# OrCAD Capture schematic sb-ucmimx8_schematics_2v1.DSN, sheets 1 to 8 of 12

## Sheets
1 01. Block Diagram: size C; title: SB-UCM-iMX8M    01. INDEX; rev: 2.0; note: 8010055003
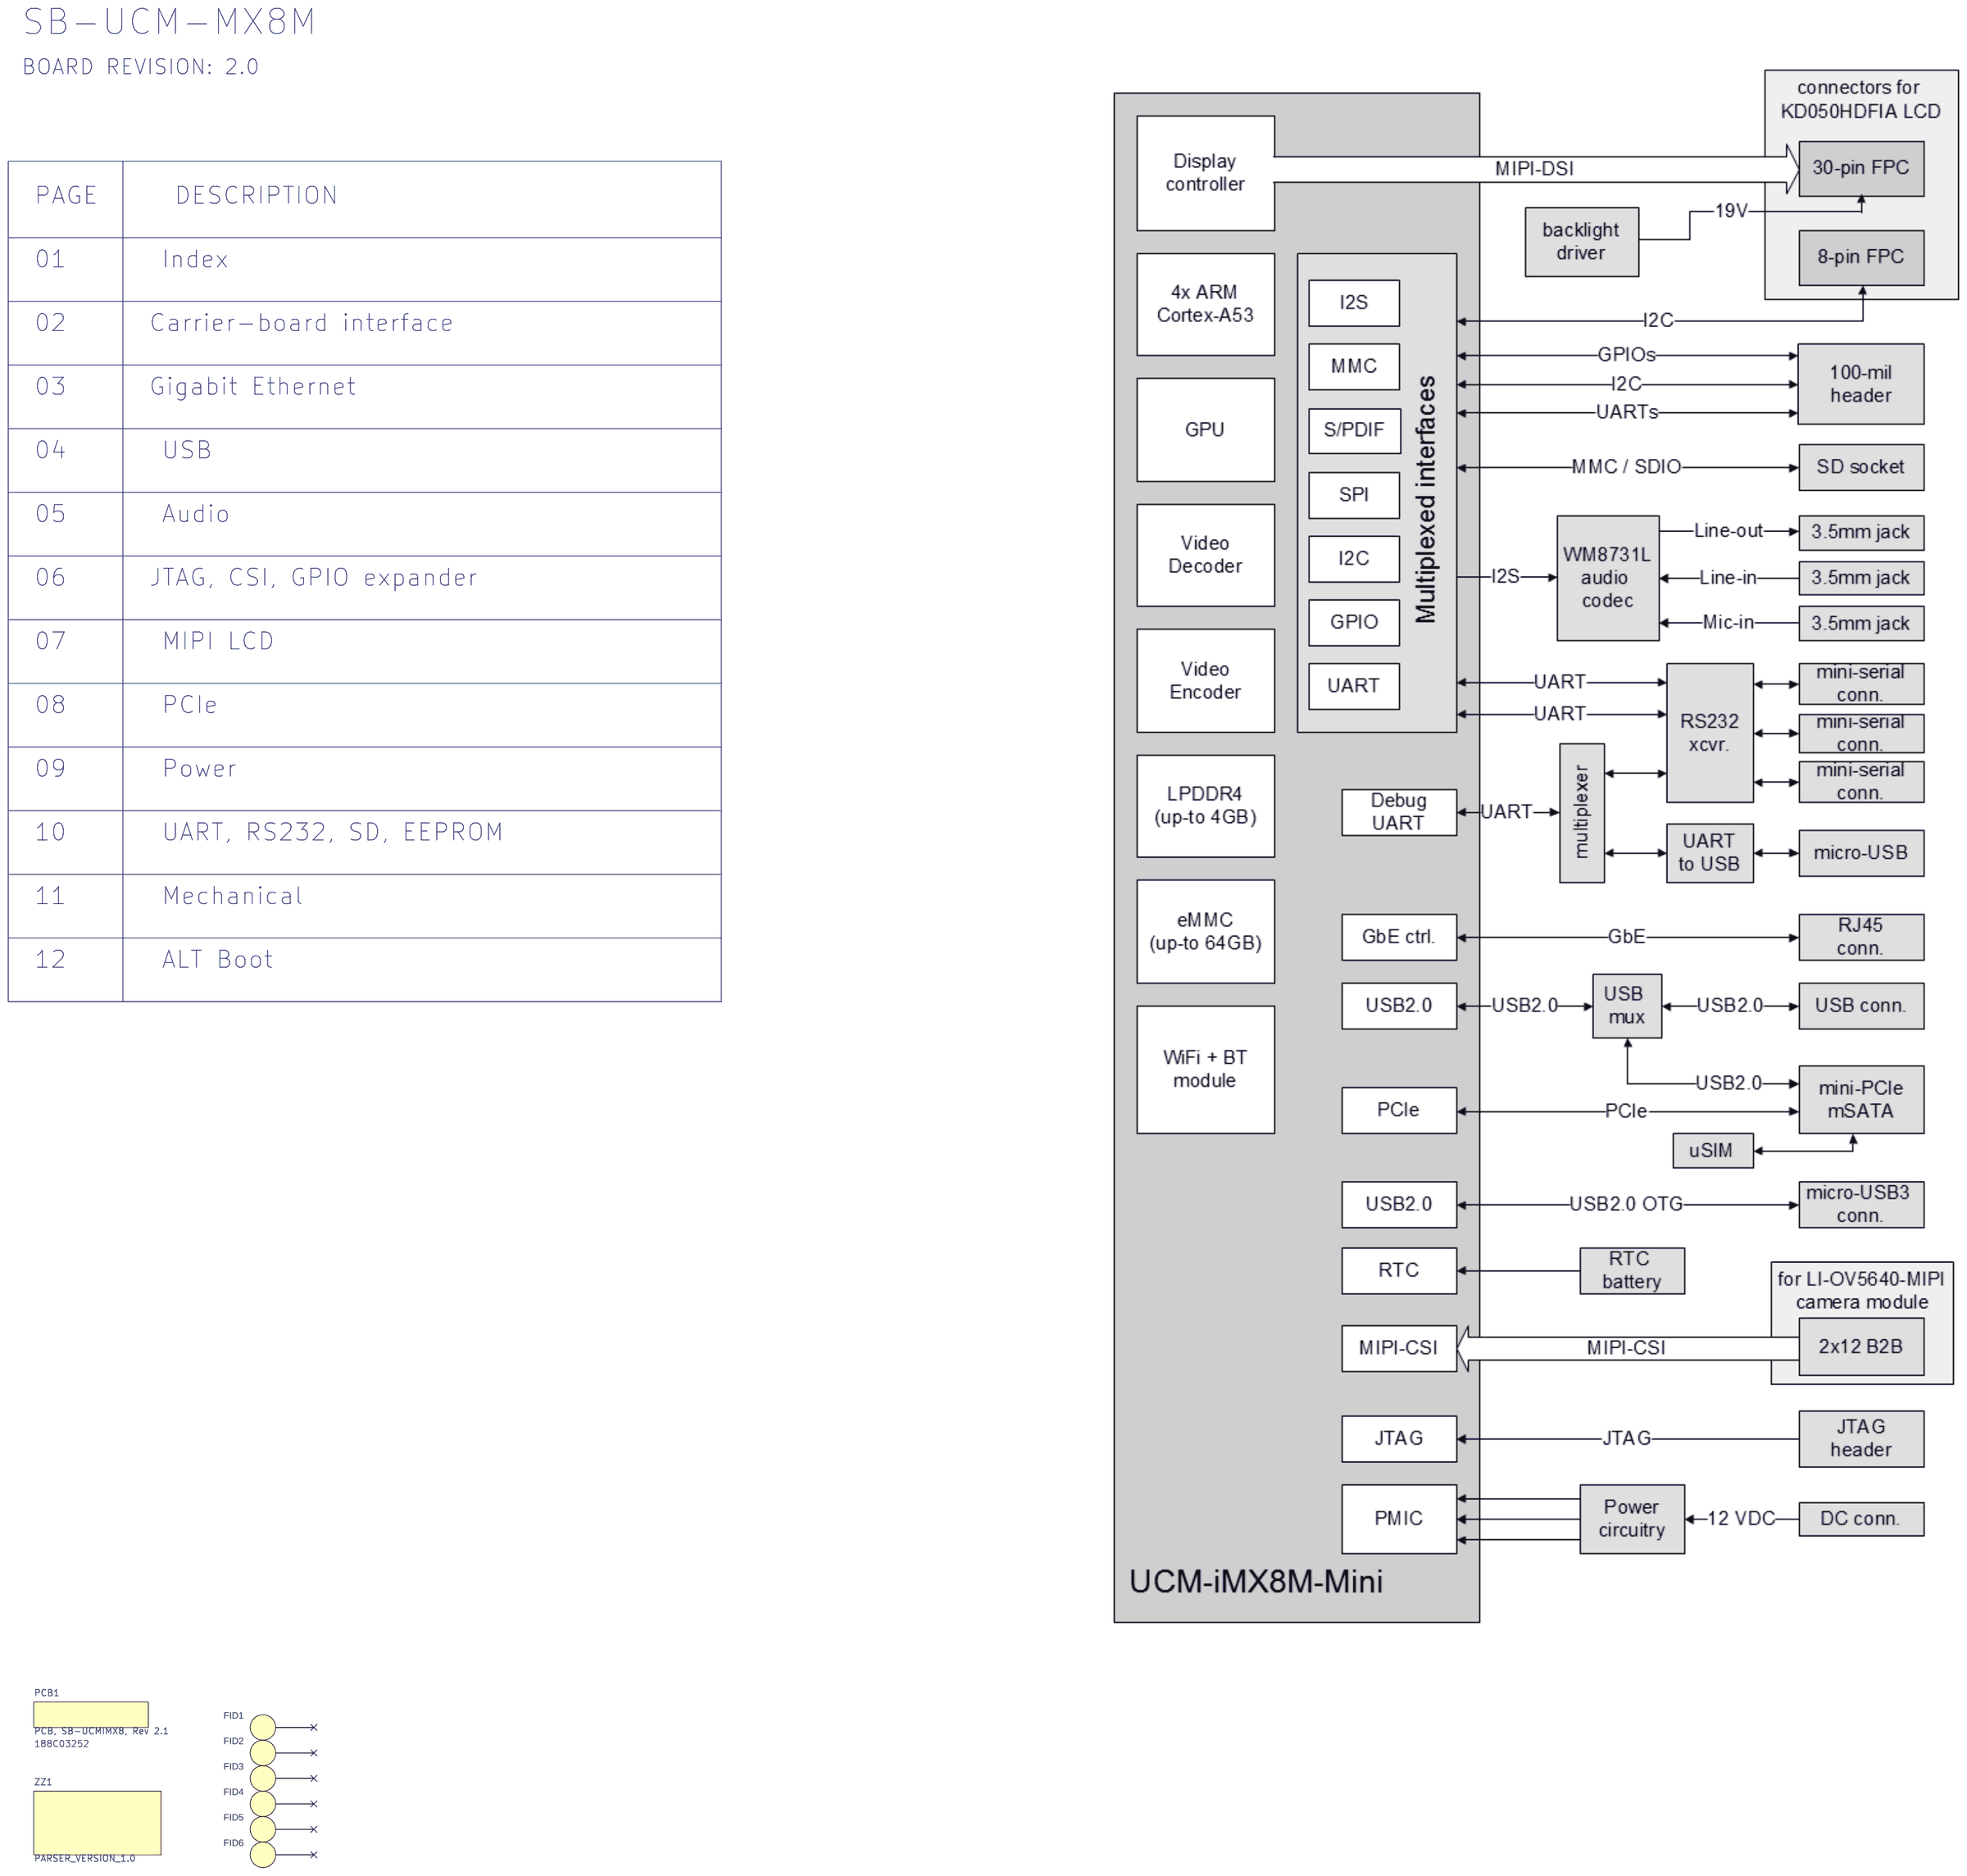
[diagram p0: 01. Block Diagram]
2 02. Carrier-board interface: size A3; title: SB-UCM-iMX8M  02. Carrier; note: 8000103001
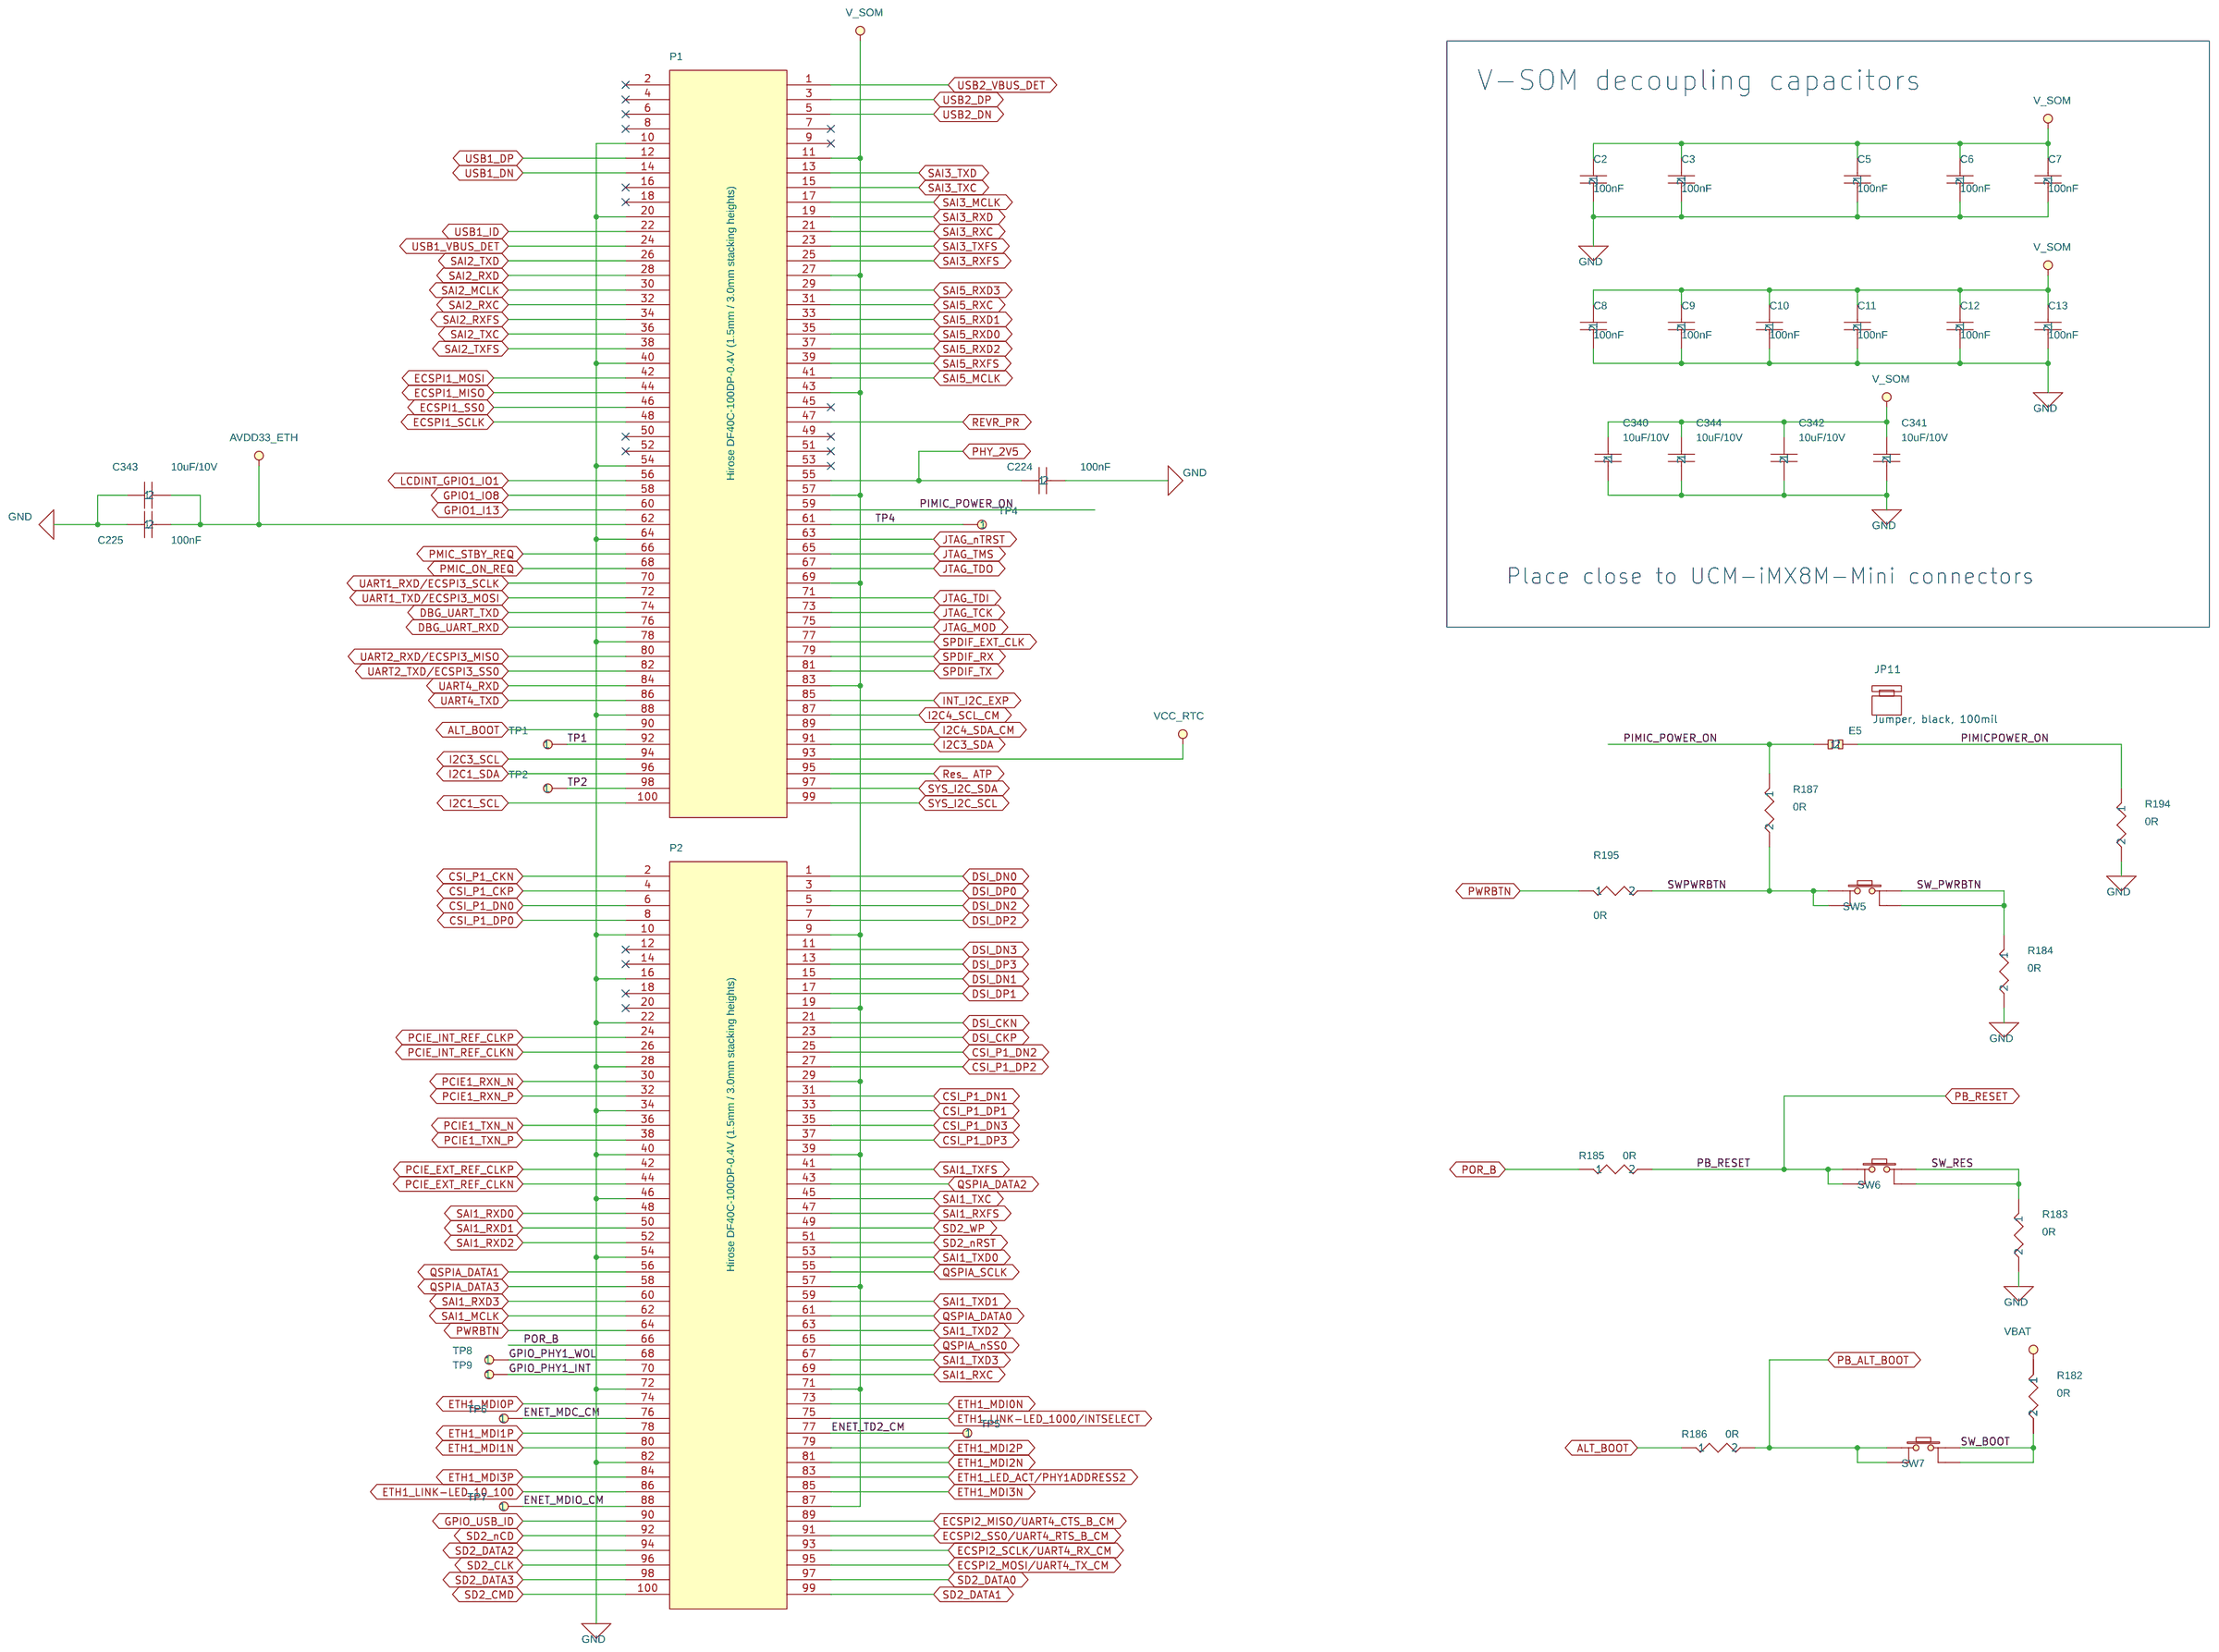
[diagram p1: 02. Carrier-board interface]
3 03. Gigabit Ethernet: size A4; title: SB-UCM-iMX8M      03. Gigabit Ethernet; note: 8000103001
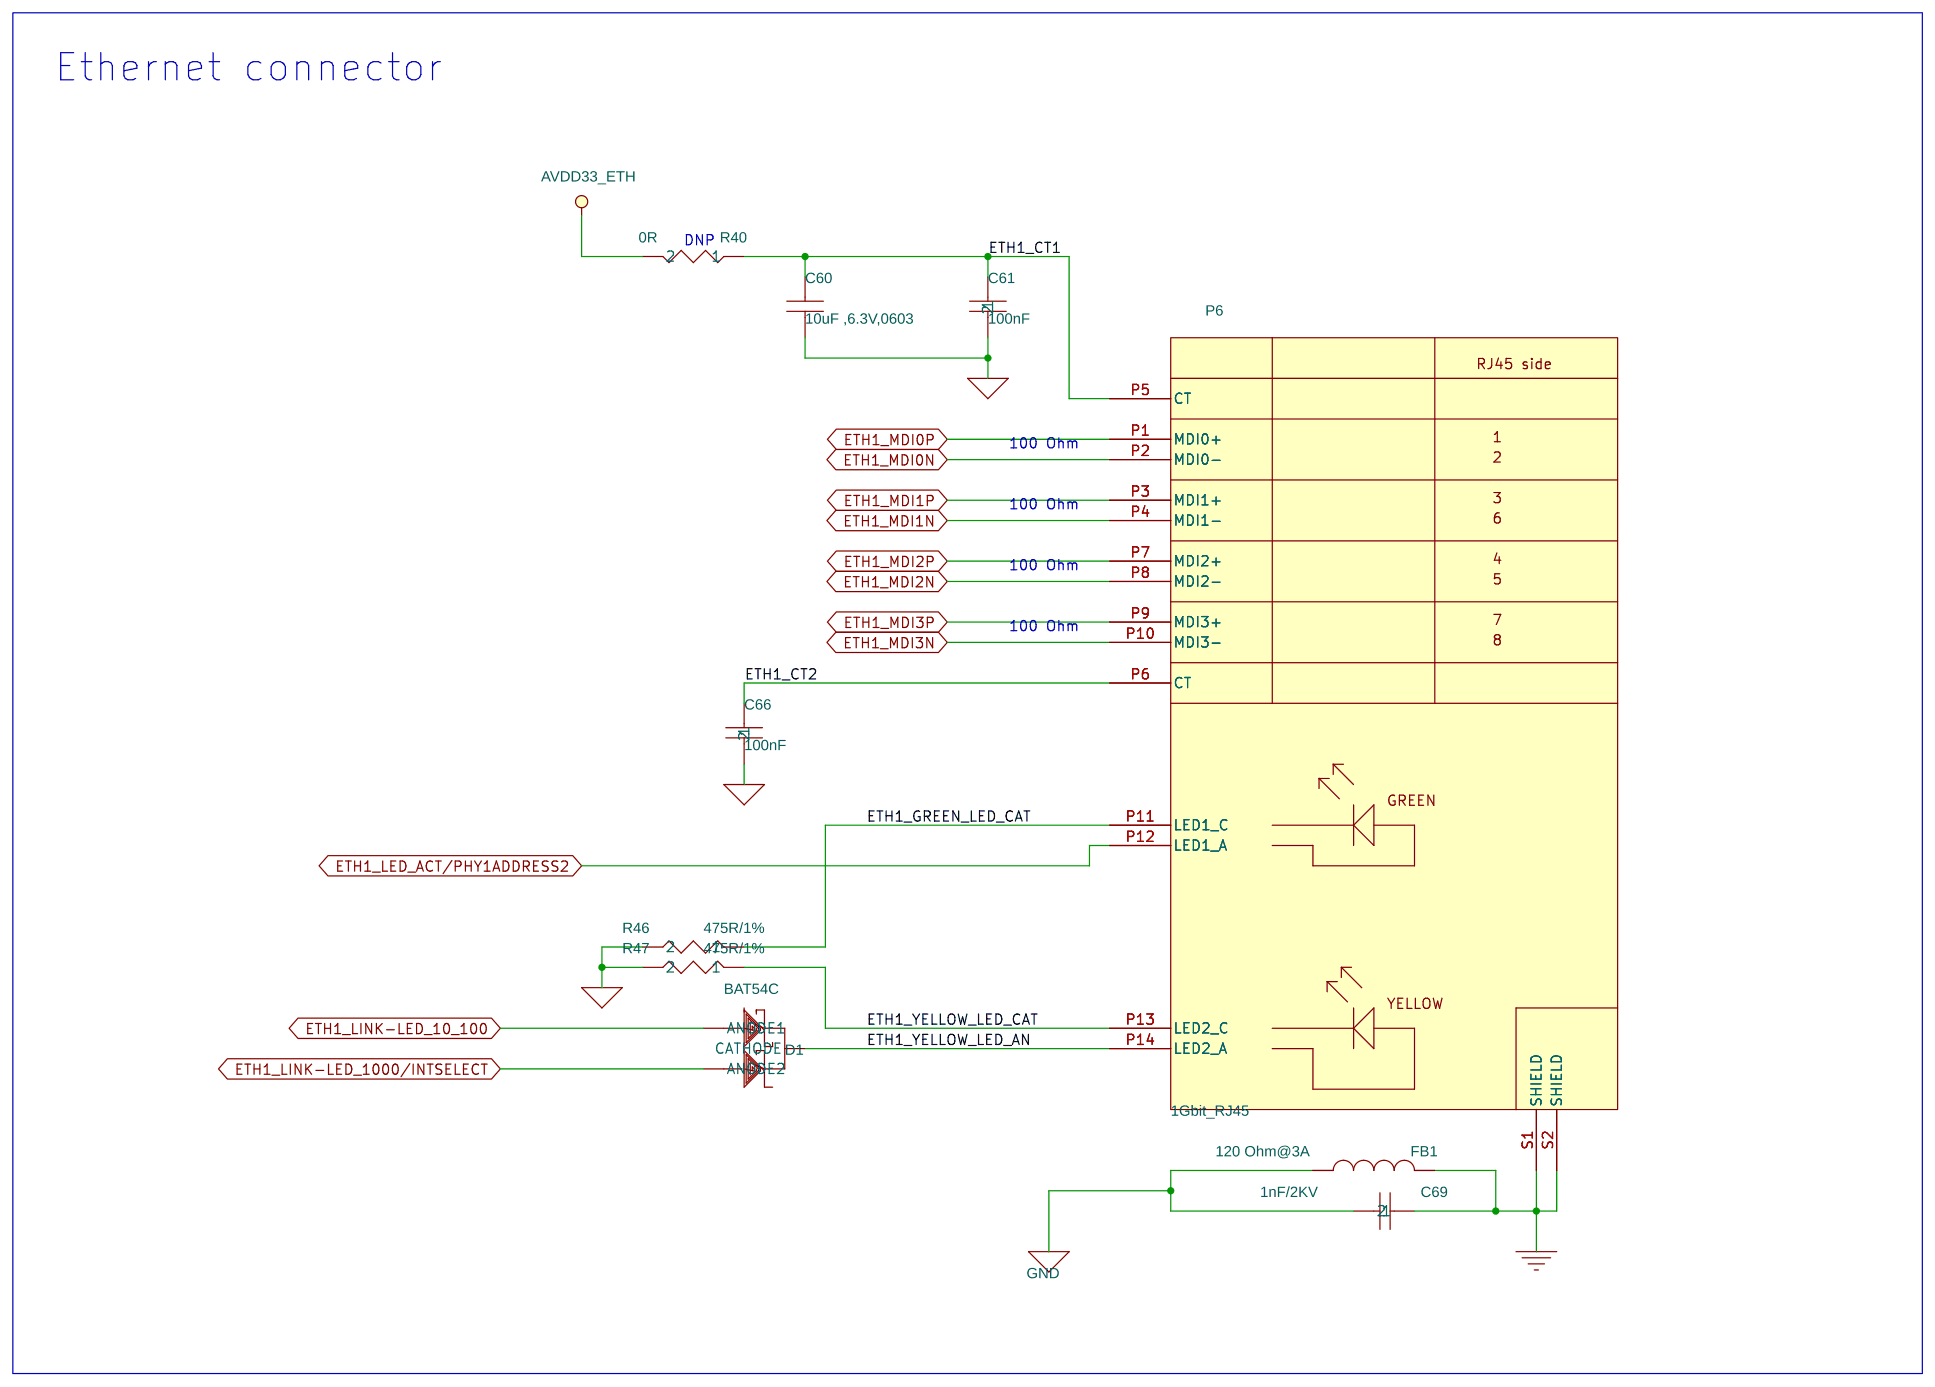
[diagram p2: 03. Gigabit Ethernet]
4 04. USB: size A3; title: SB-UCM-iMX8M    04. USB; note: 8000103001
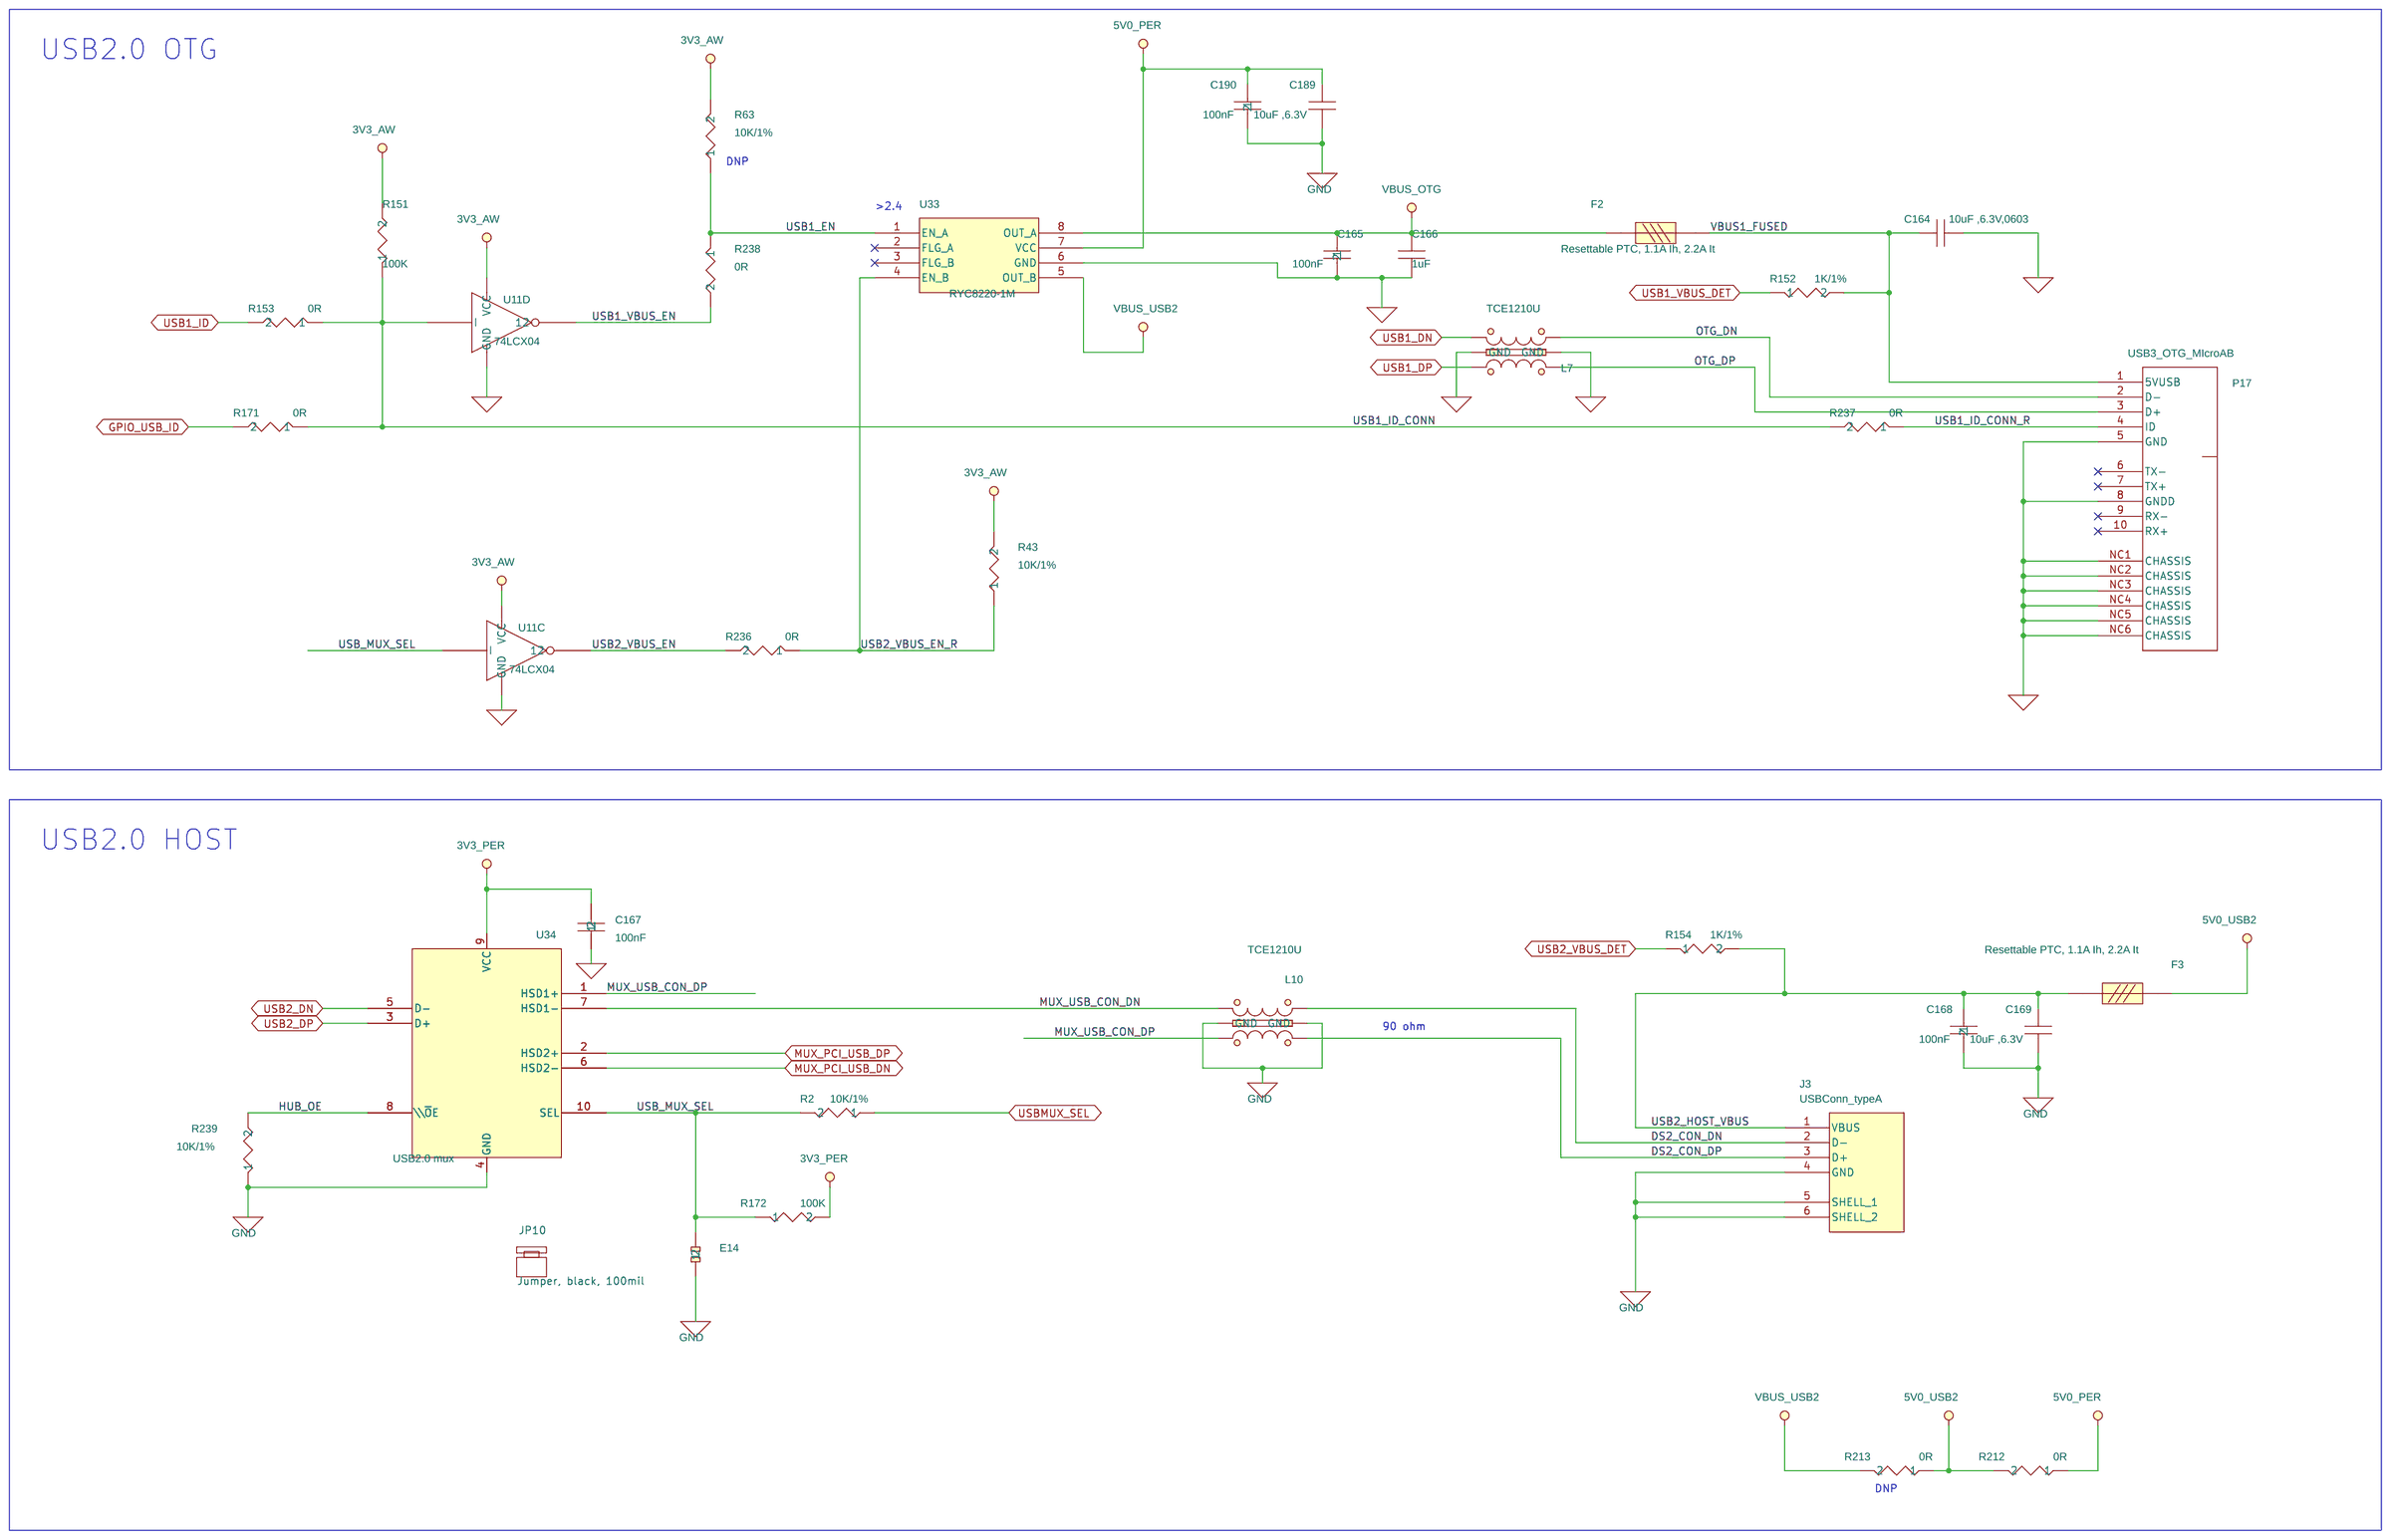
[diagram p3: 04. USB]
5 12. ALT boot: size C; title: SB-UCM-iMX8M    12.ALT-BOOT; note: 8000103001
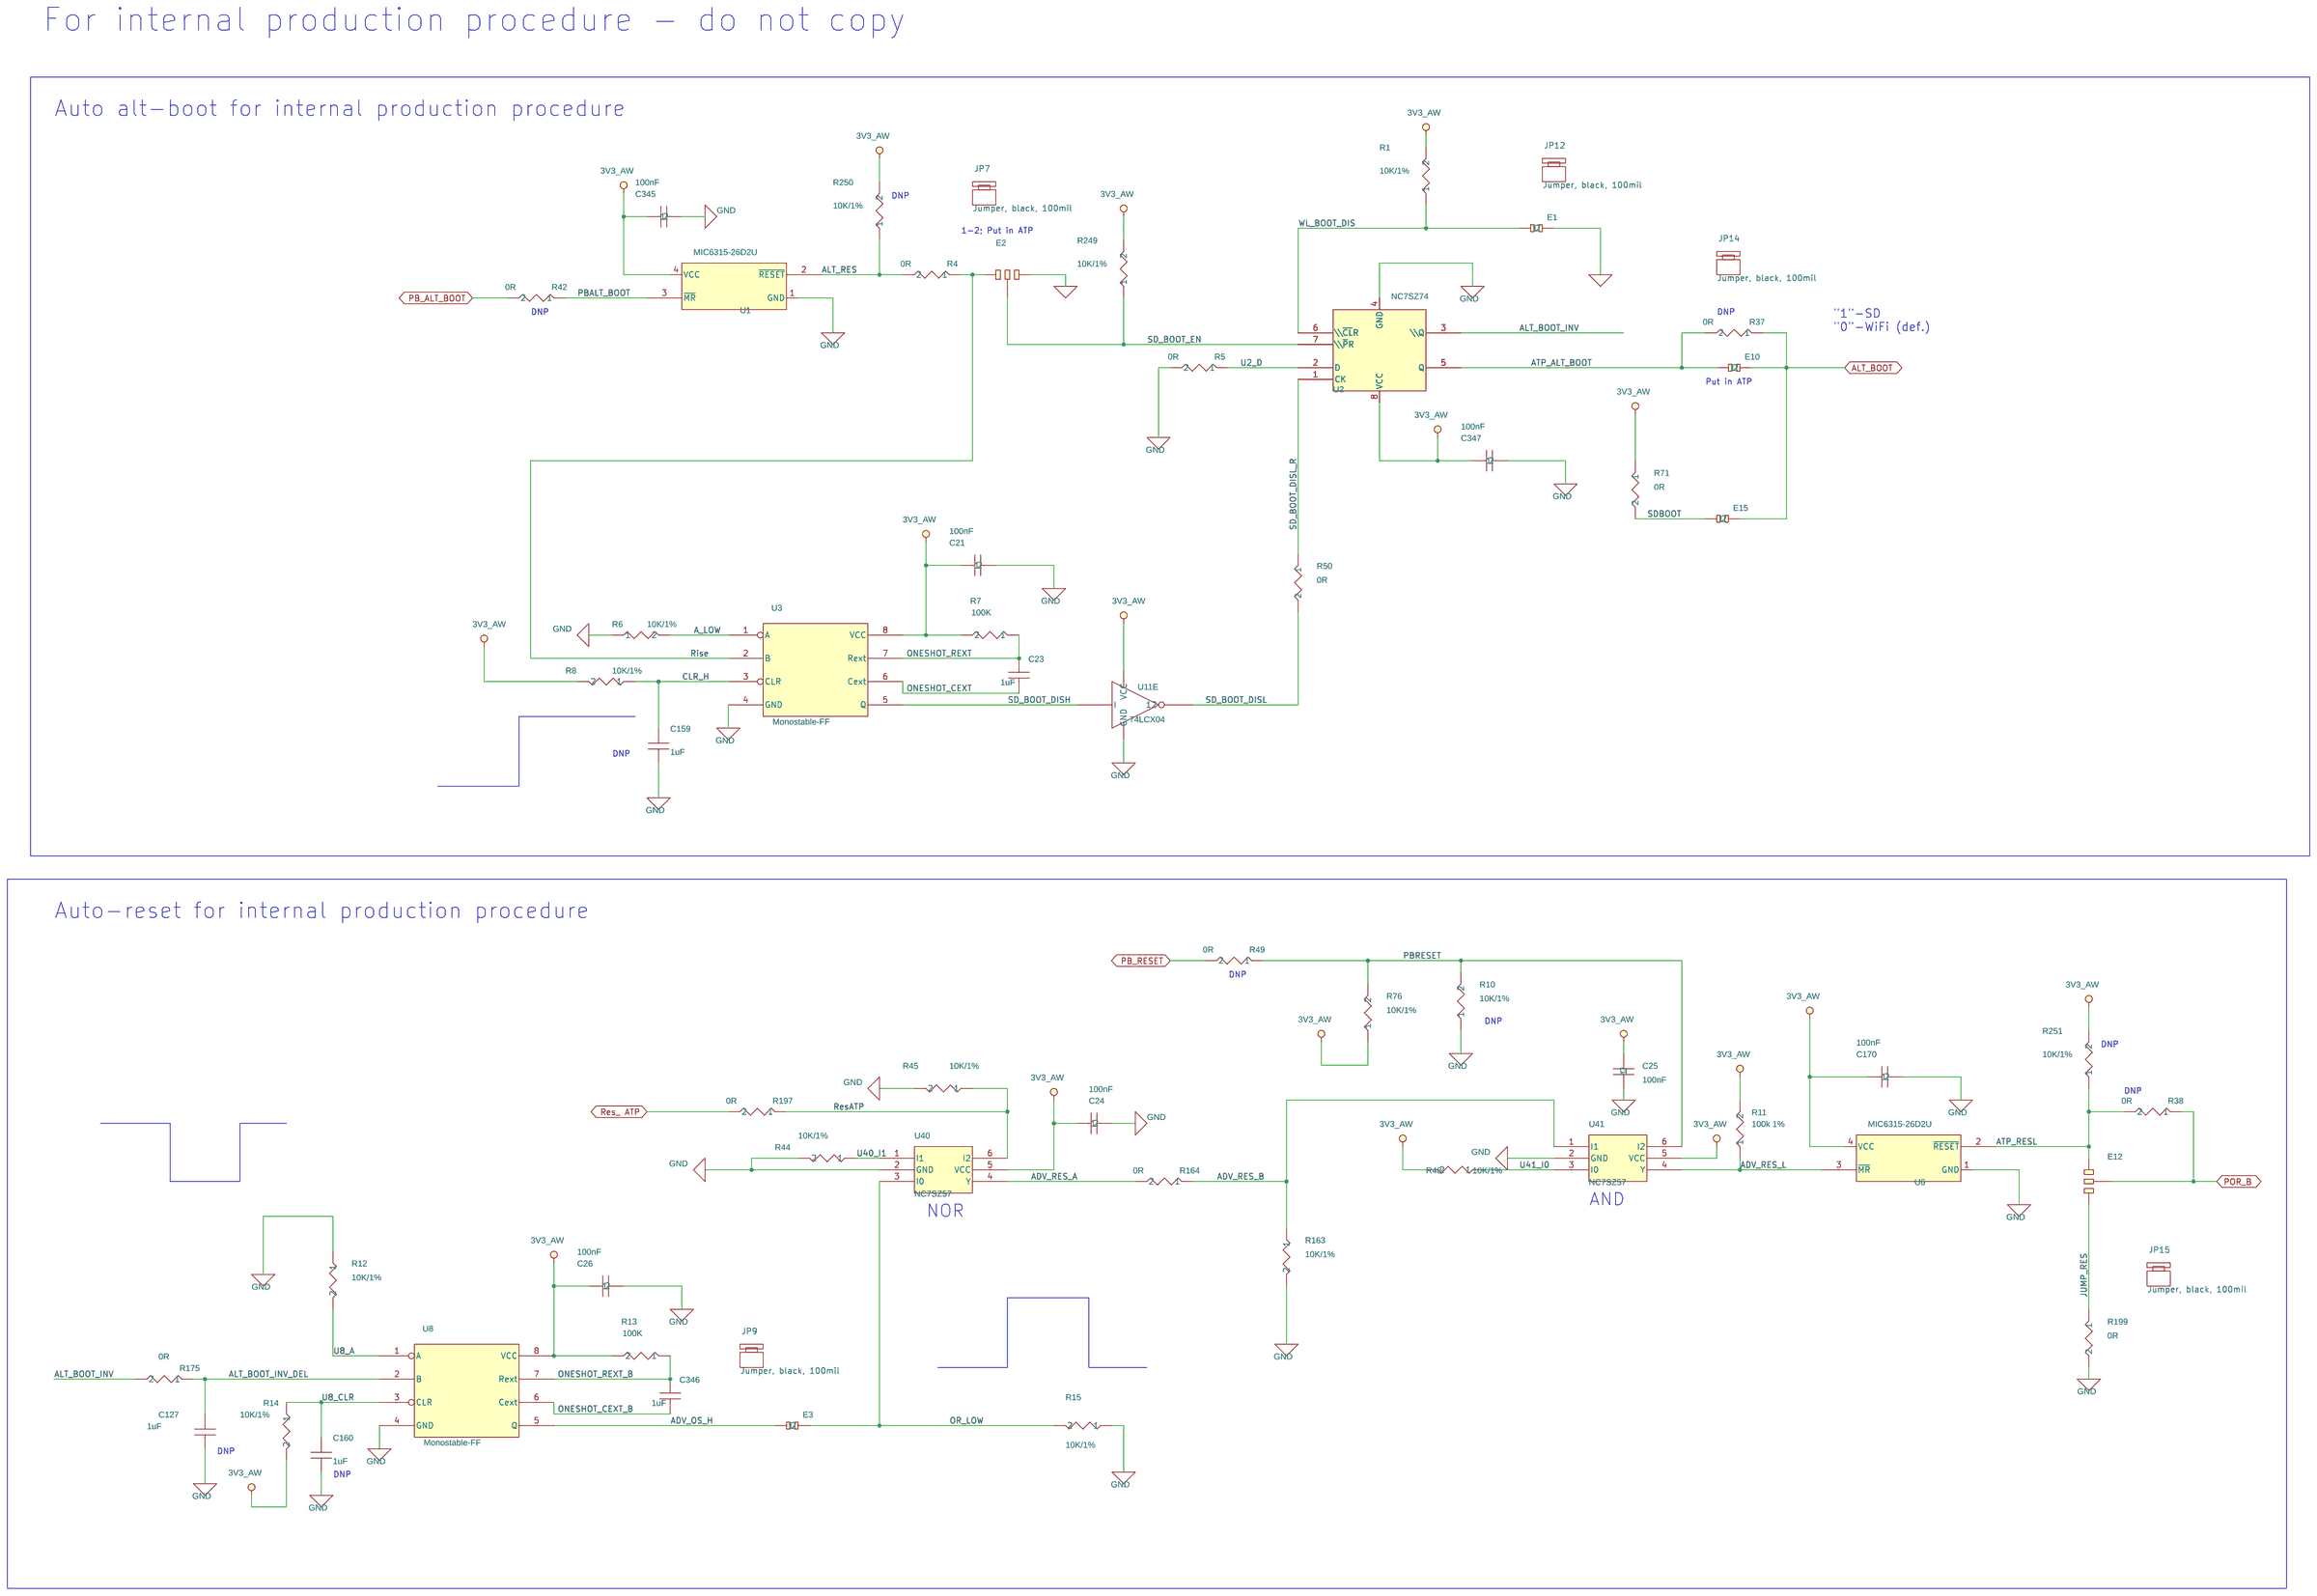
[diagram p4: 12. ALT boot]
6 05. Audio: size B; title: SB-UCM-iMX8M      05. AUDIO,SPDIF; note: 8000103001
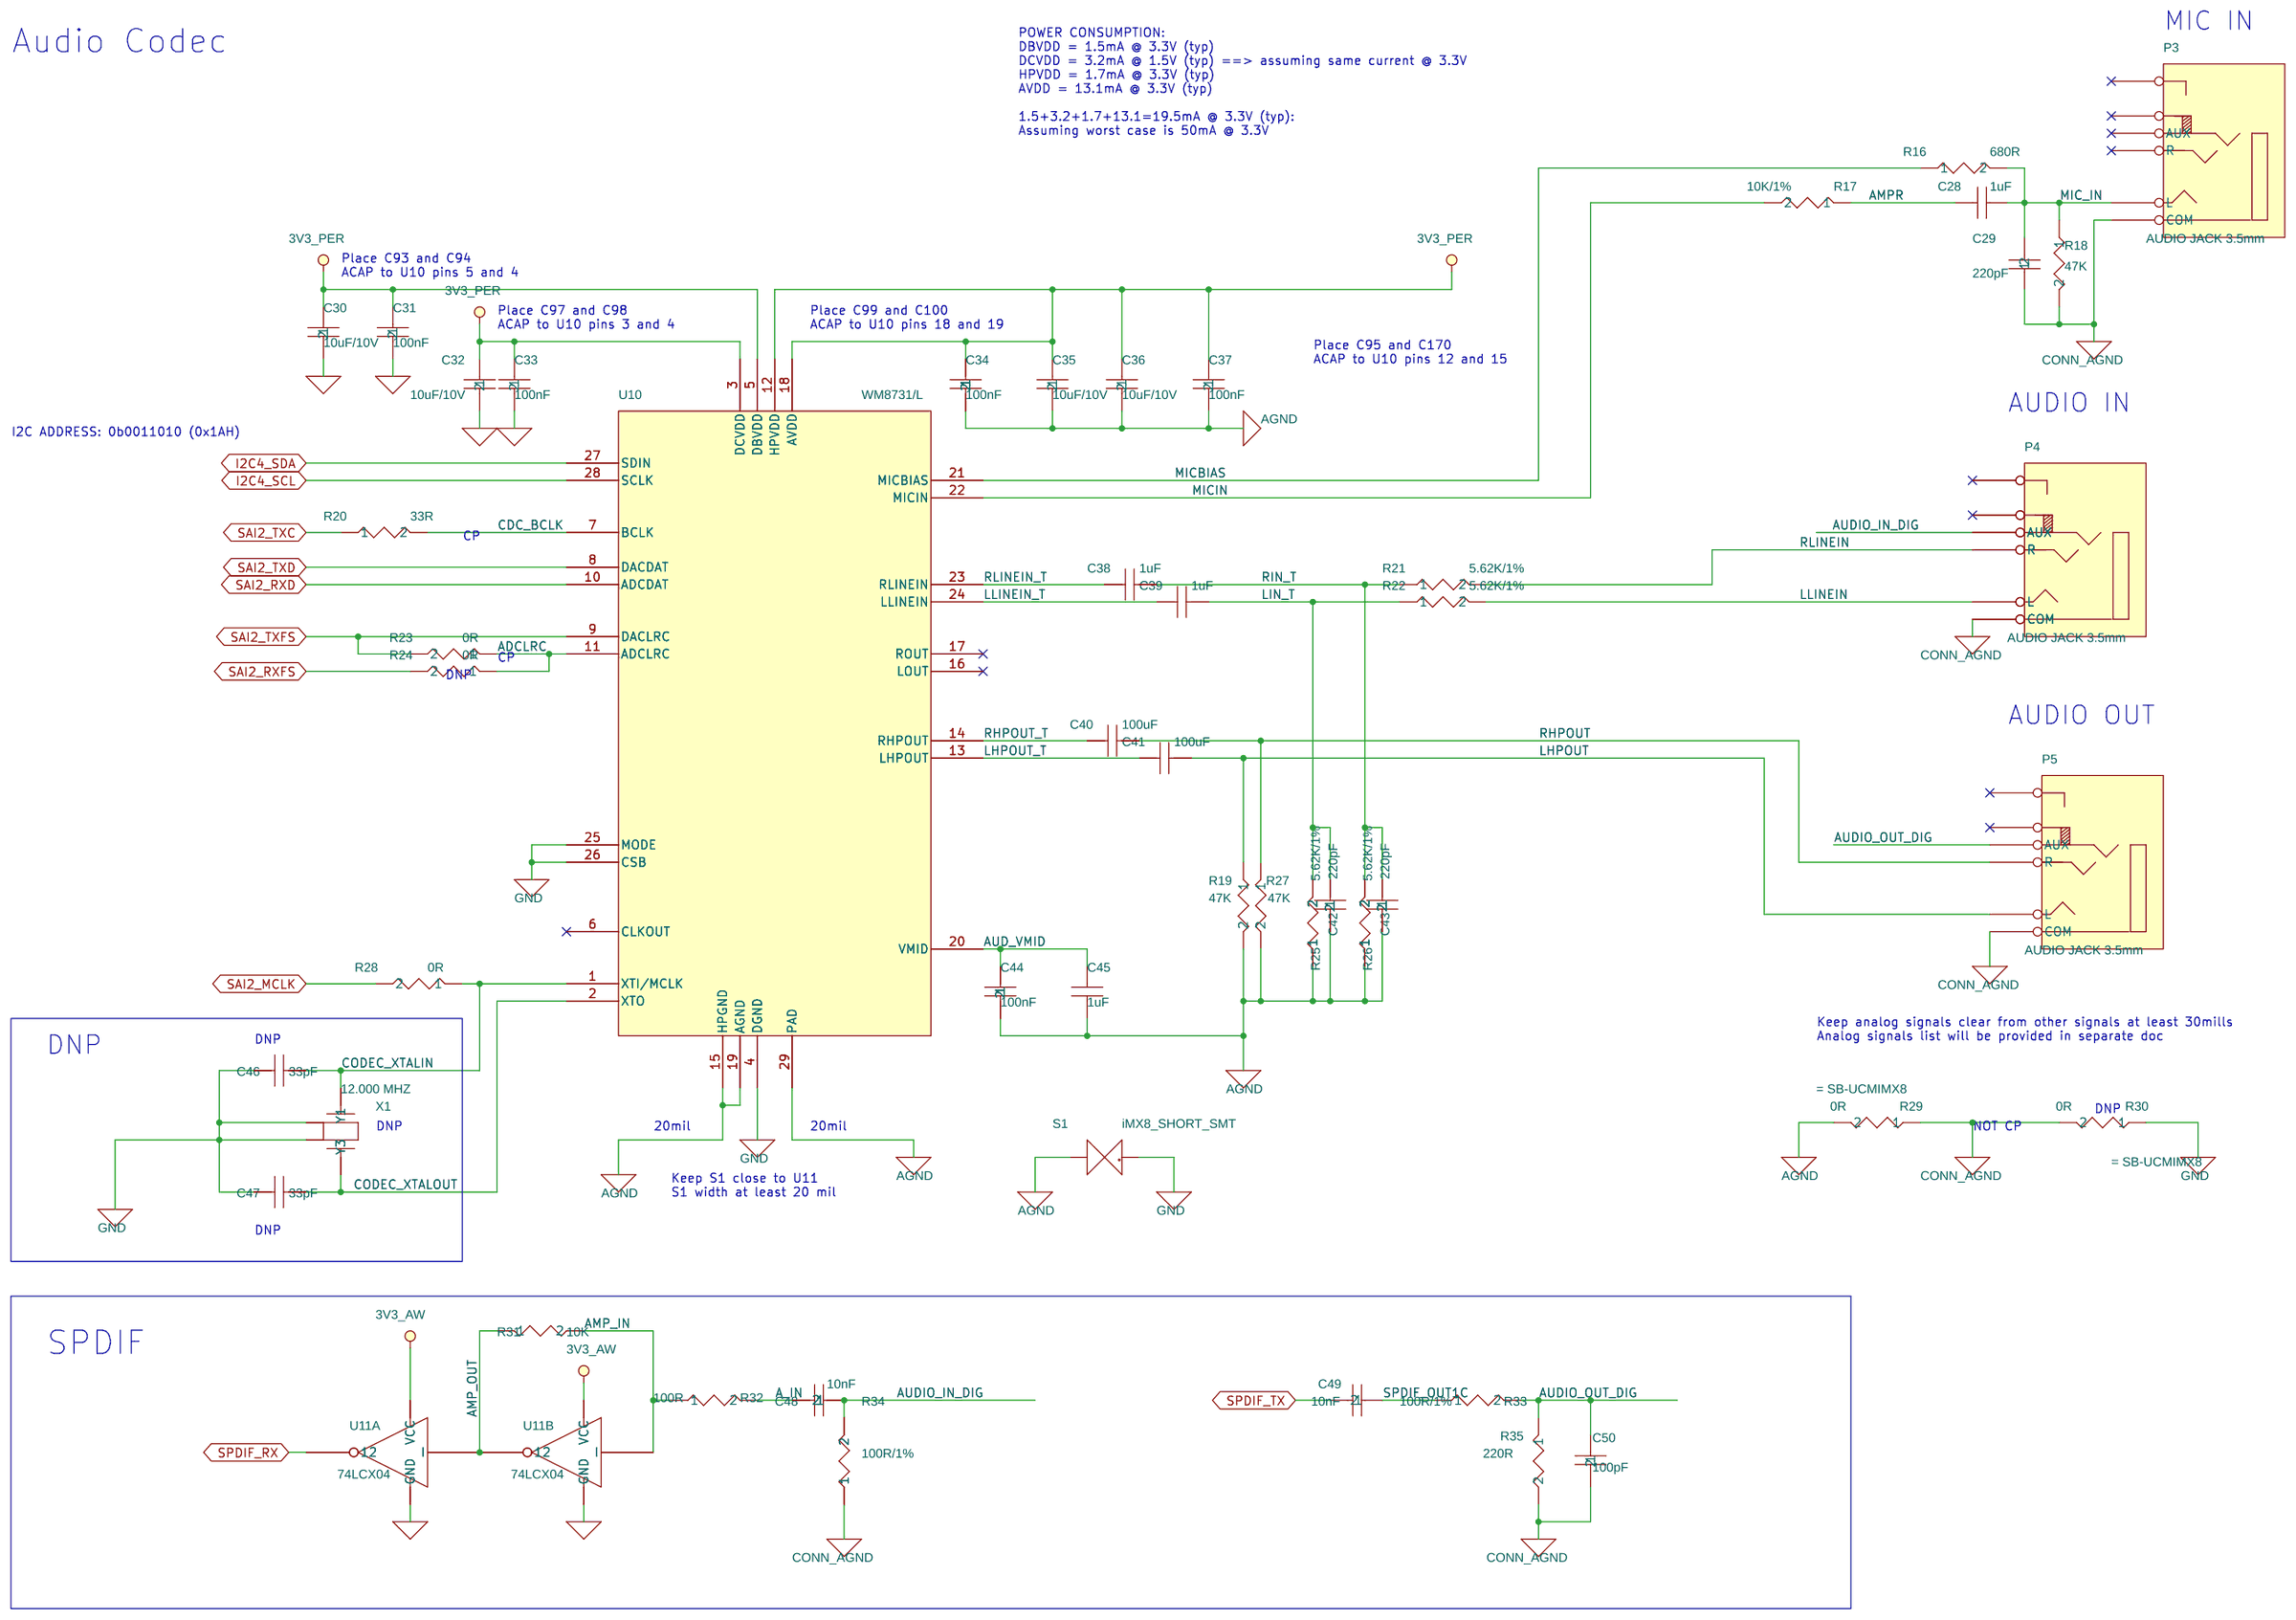
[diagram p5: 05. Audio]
7 06. JTAG, CSI, GPIO expander: size A2; title: SB-UCM-iMX8M    06. HDMI,CSI.MISK; note: 8000103001
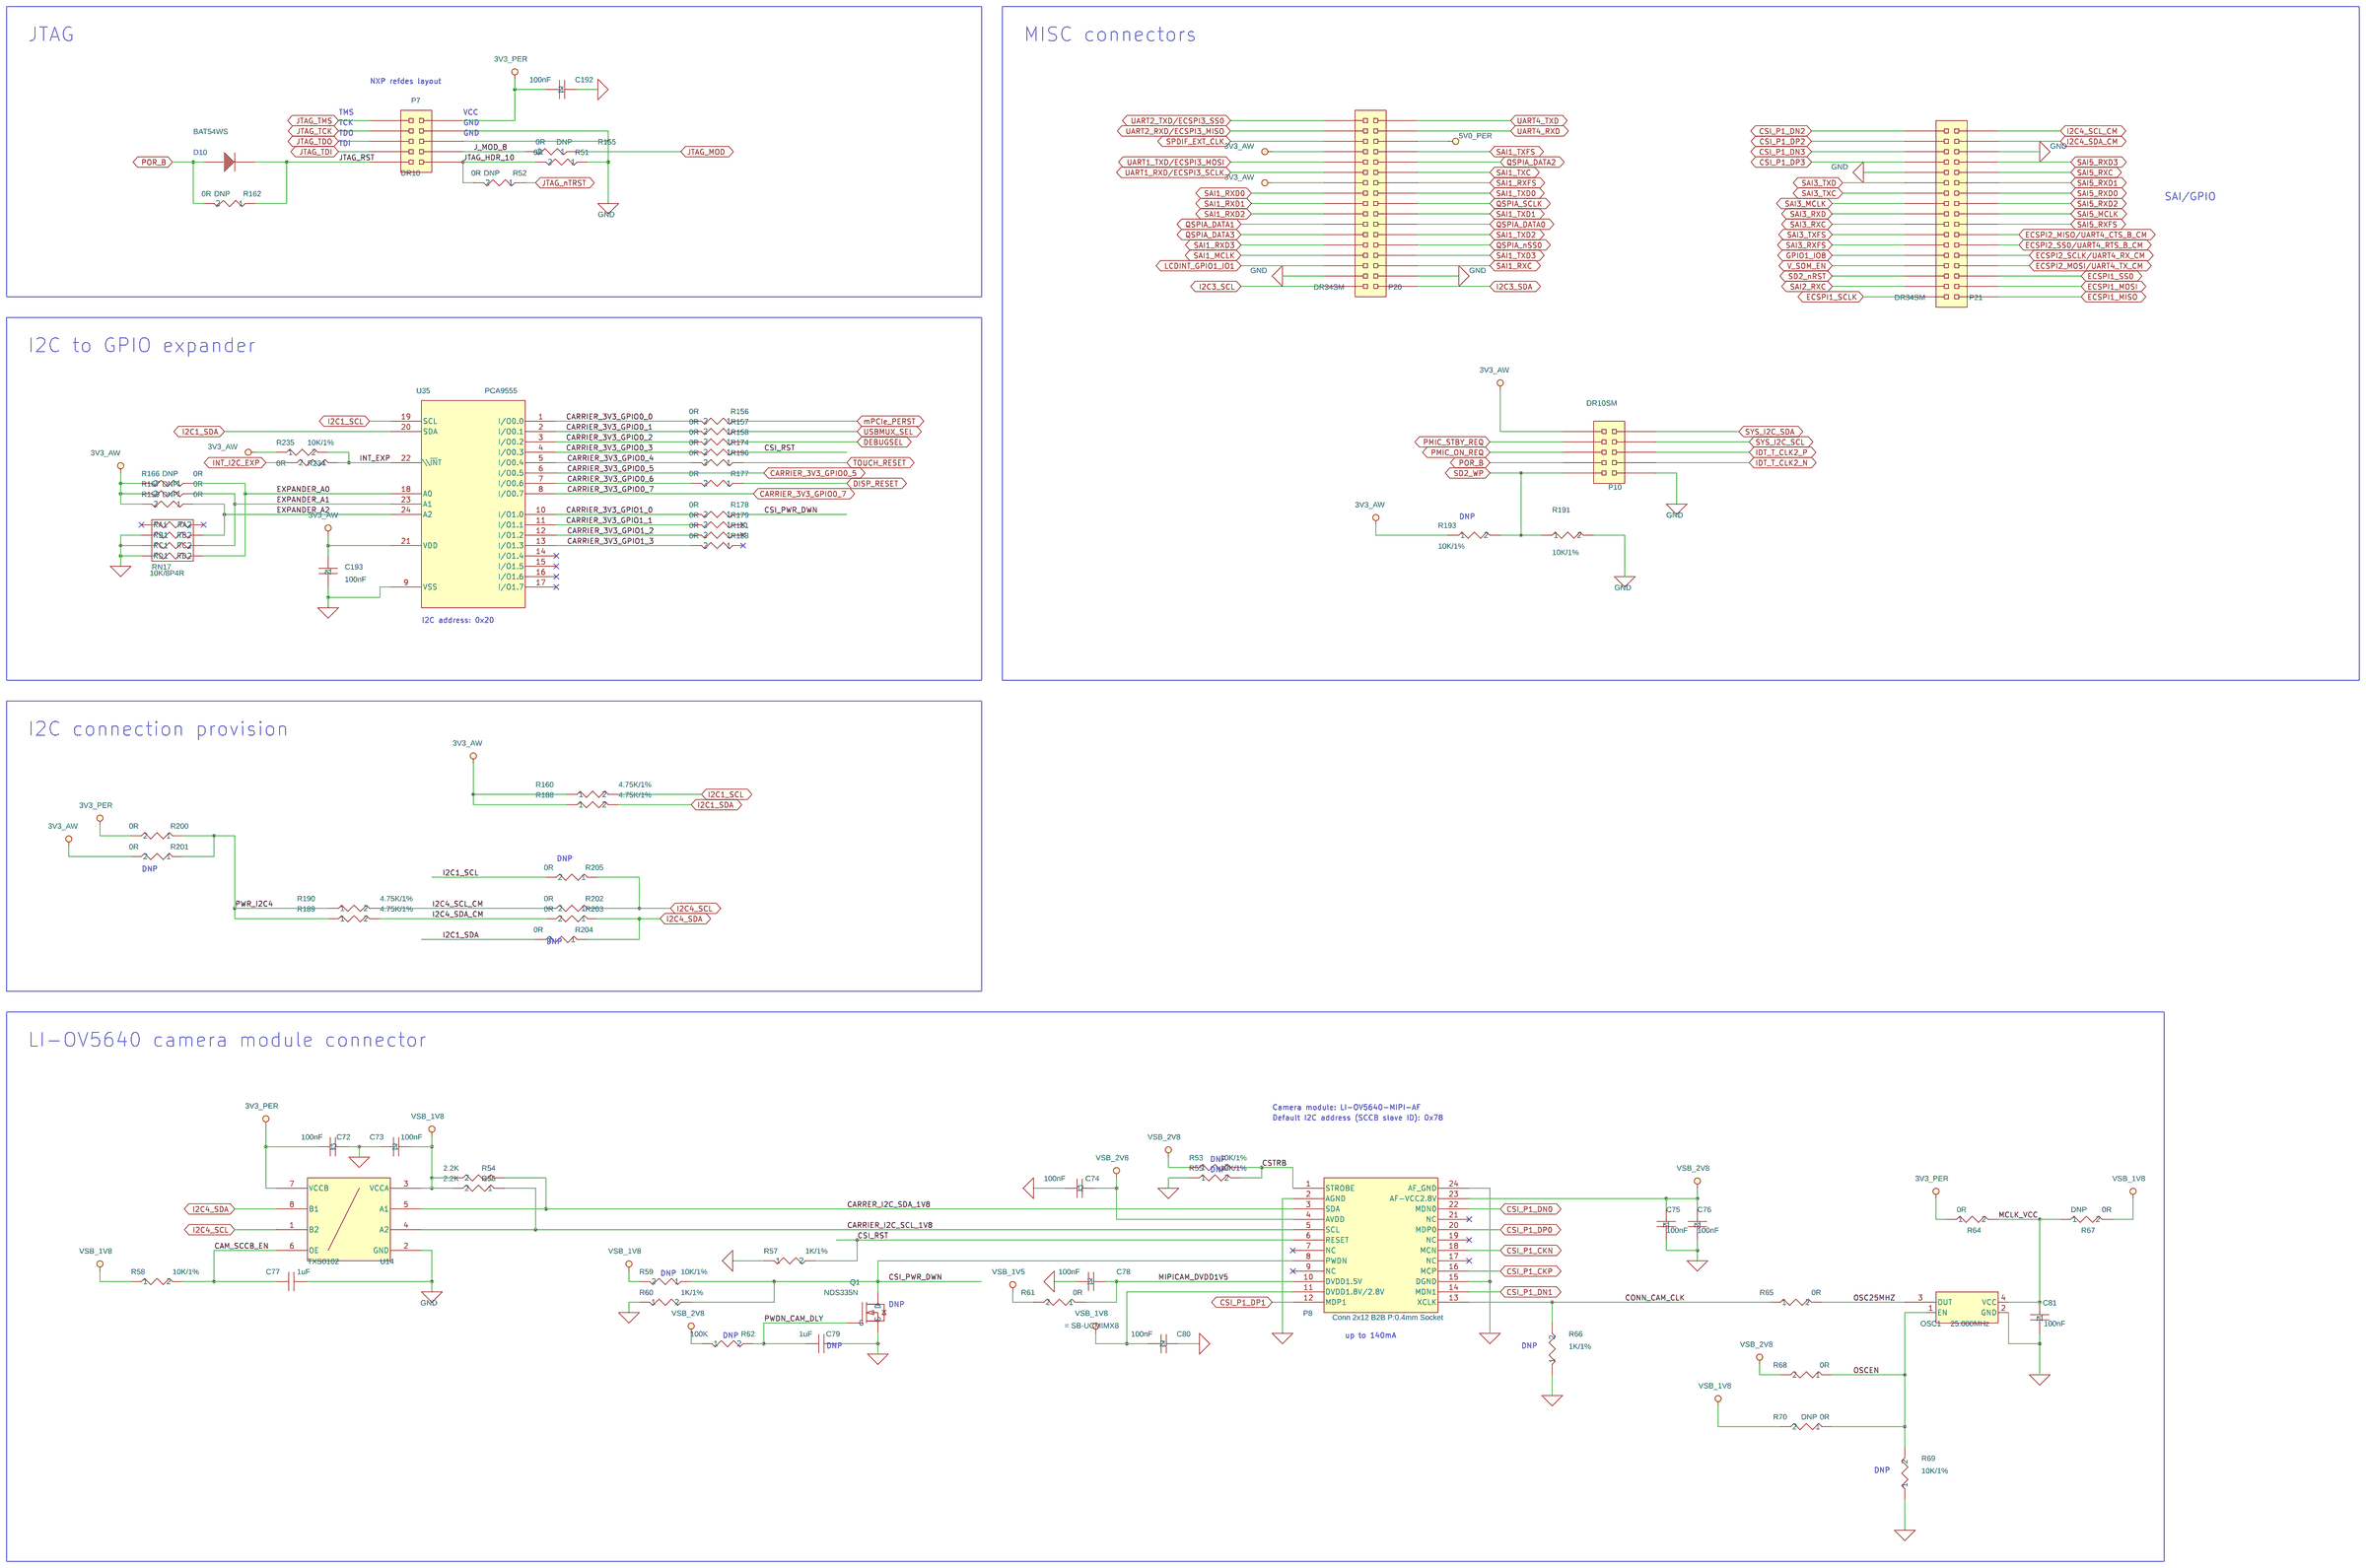
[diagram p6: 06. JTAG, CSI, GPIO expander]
8 07. MIPI LCD: size A3; title: SB-UCM-iMX8M   07. MIPI-LCD; note: 8000103001
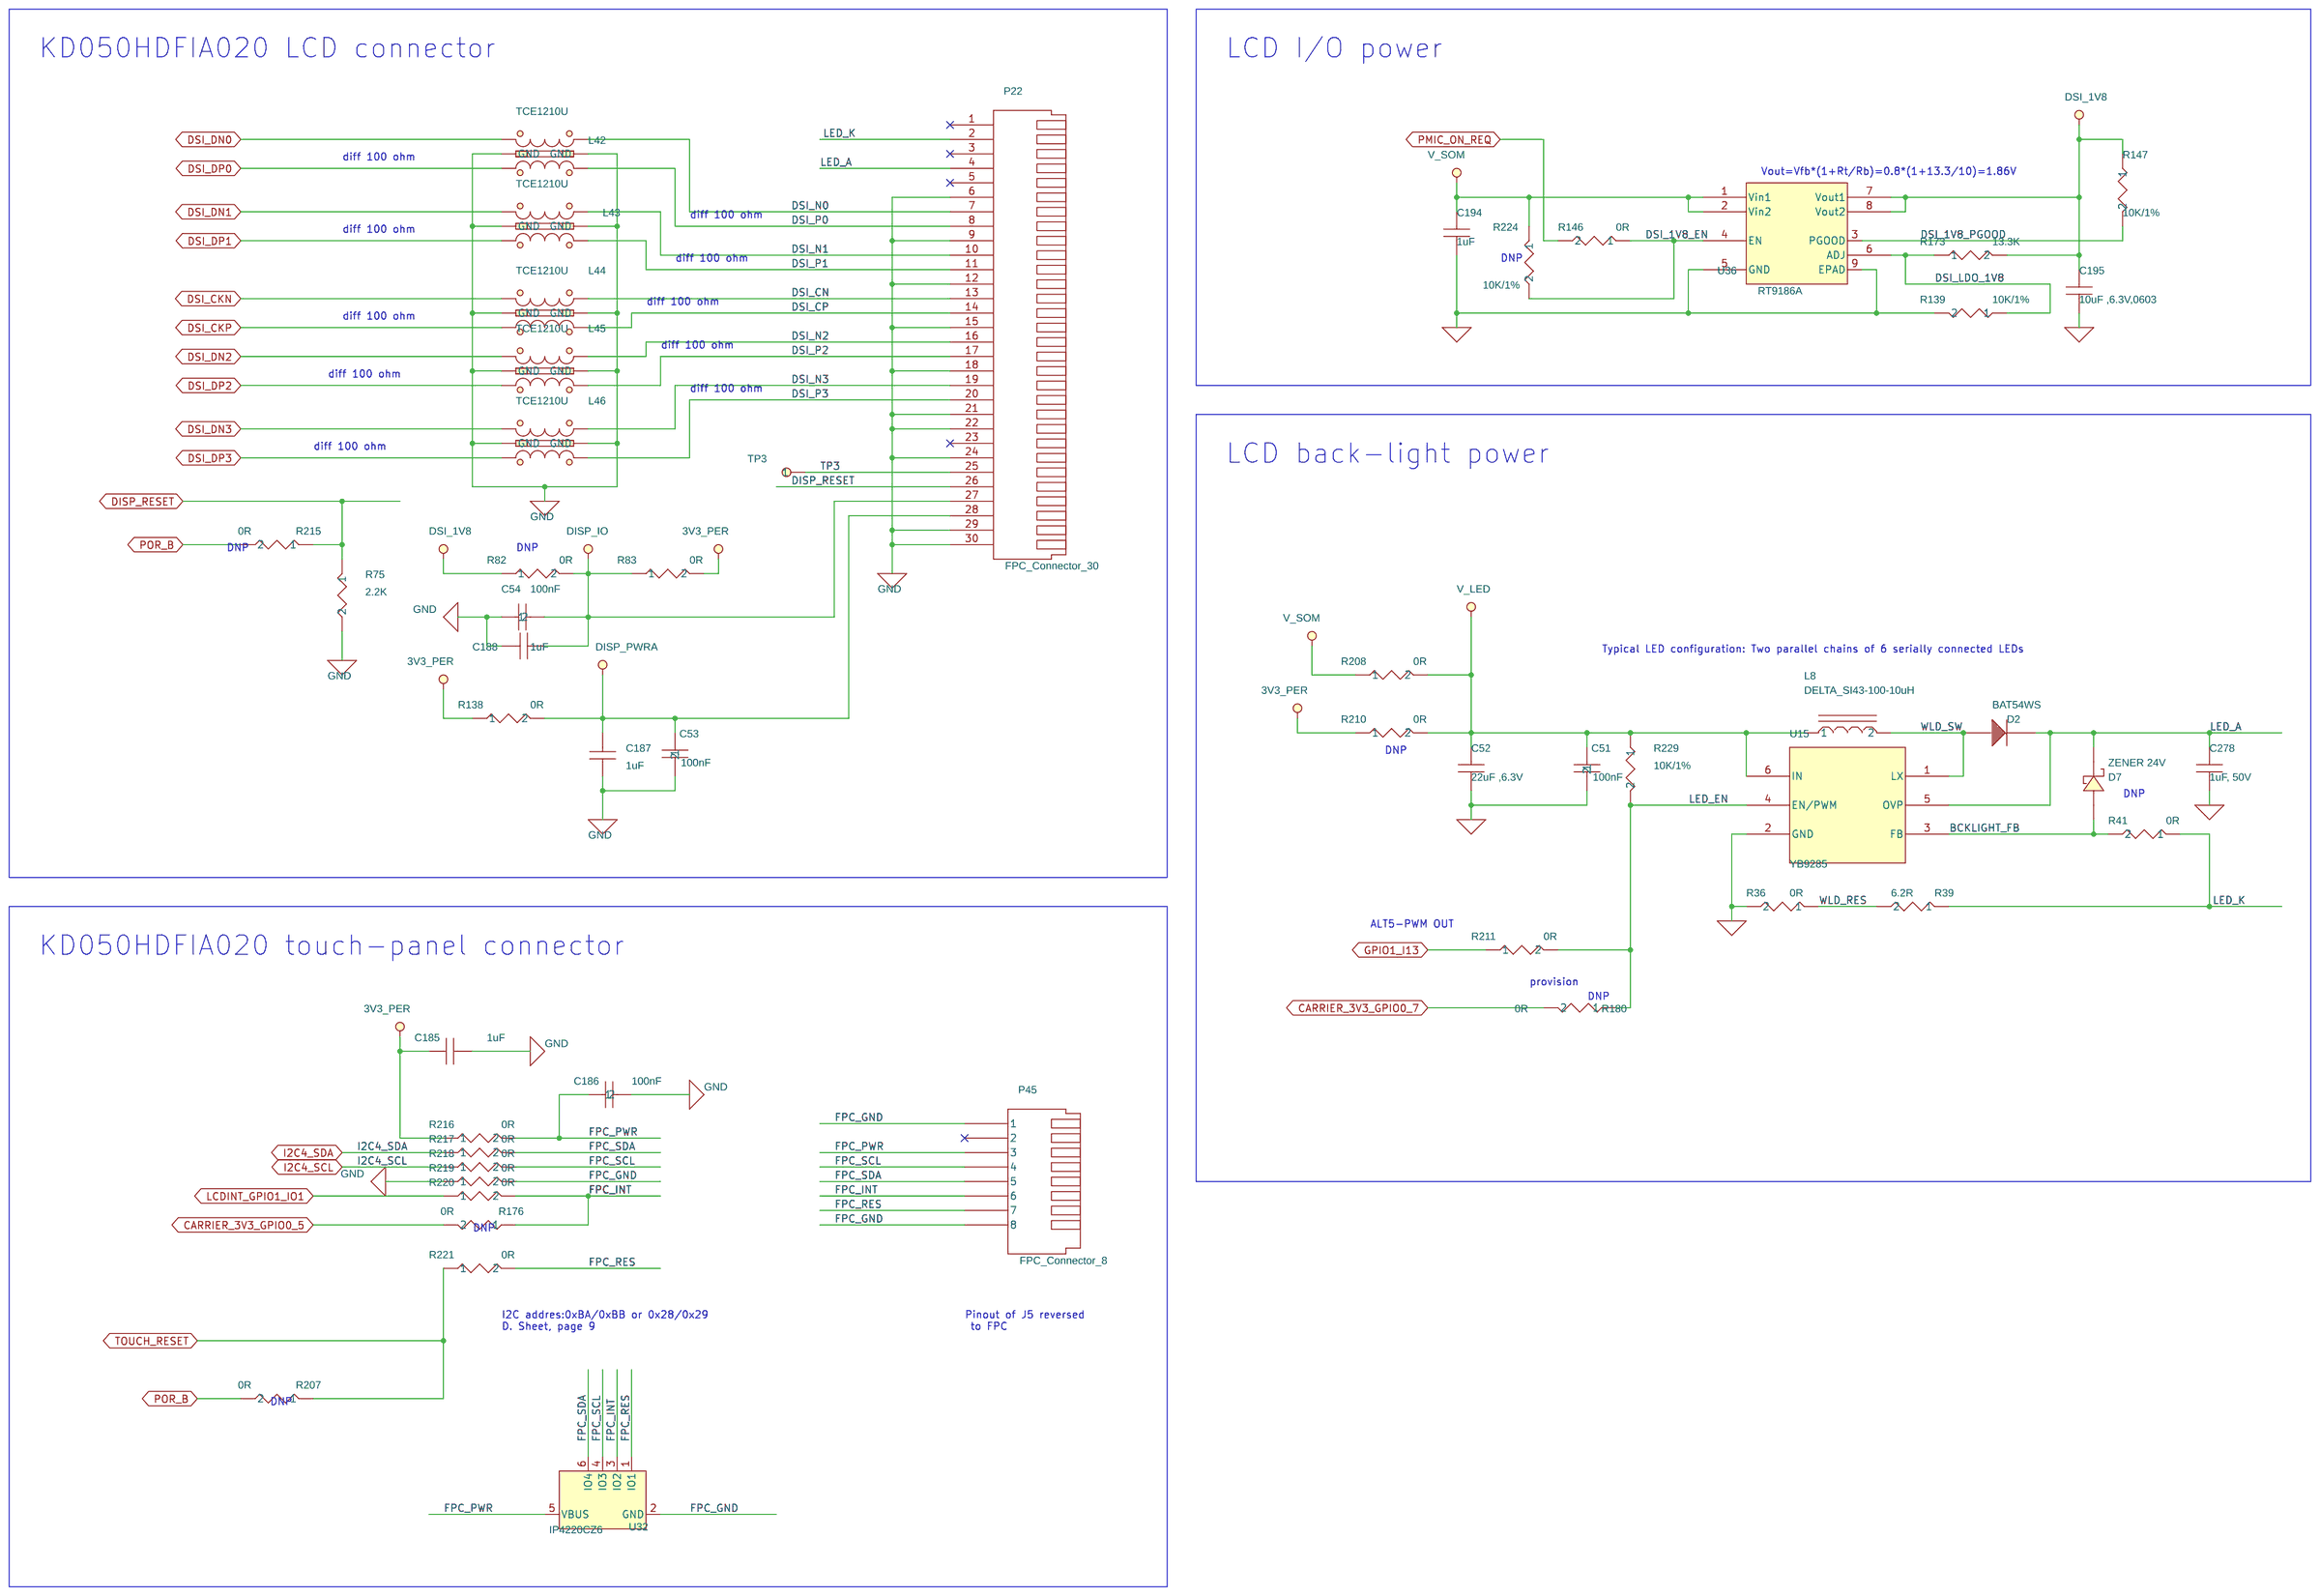
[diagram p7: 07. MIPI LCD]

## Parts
sheet 01. Block Diagram
FID1  FIDUCIAL  [FIDUCIAL]
FID2  FIDUCIAL  [FIDUCIAL]
FID3  FIDUCIAL  [FIDUCIAL]
FID4  FIDUCIAL  [FIDUCIAL]
FID5  FIDUCIAL  [FIDUCIAL]
FID6  FIDUCIAL  [FIDUCIAL]
PCB1  PCB, SB-UCMIMX8, Rev 2.1
ZZ1  PARSER_VERSION_1.0
sheet 02. Carrier-board interface
C2  100nF  [RC0402]
C3  100nF  [RC0402]
C5  100nF  [RC0402]
C6  100nF  [RC0402]
C7  100nF  [RC0402]
C8  100nF  [RC0402]
C9  100nF  [RC0402]
C10  100nF  [RC0402]
C11  100nF  [RC0402]
C12  100nF  [RC0402]
C13  100nF  [RC0402]
C224  100nF  [RC0402]
C225  100nF  [RC0402]
C340  10uF/10V  [0402]
C341  10uF/10V  [0402]
C342  10uF/10V  [0402]
C343  10uF/10V  [0402]
C344  10uF/10V  [0402]
E5  HDR1X2  [1X2THHDR]
JP11  Jumper, black, 100mil
P1  Hirose DF40C-100DP-0.4V (1.5mm / 3.0mm stacking heights)  [B2B04M2X50R]
P2  Hirose DF40C-100DP-0.4V (1.5mm / 3.0mm stacking heights)  [B2B04M2X50R]
R182  0R  [RC0402]
R183  0R  [RC0402]
R184  0R  [RC0402]
R185  0R  [RC0402]
R186  0R  [RC0402]
R187  0R  [RC0402]
R194  0R  [RC0402]
R195  0R  [RC0402]
SW5  PushB  [TACTSW6x6SM]
SW6  PushB  [TACTSW6x6SM]
SW7  PushB  [TACTSW6x6SM]
TP1  TESTPOINT  [TESTPOINT]
TP2  TESTPOINT  [TESTPOINT]
TP4  TESTPOINT  [TESTPOINT]
TP5  TESTPOINT  [TESTPOINT]
TP6  TESTPOINT  [TESTPOINT]
TP7  TESTPOINT  [TESTPOINT]
TP8  TESTPOINT  [TESTPOINT]
TP9  TESTPOINT  [TESTPOINT]
sheet 03. Gigabit Ethernet
C60  10uF ,6.3V,0603  [RC0603]
C61  100nF  [RC0402]
C66  100nF  [RC0402]
C69  1nF/2KV  [C1812]
D1  BAT54C  [SOT23]
FB1  120 Ohm@3A  [1206]
P6  1Gbit_RJ45  [DUSBRJ-1G]
R40  0R  [RC0402]
R46  475R/1%  [RC0402]
R47  475R/1%  [RC0402]
sheet 04. USB
C164  10uF ,6.3V,0603  [C0603-08]
C165  100nF  [RC0402]
C166  1uF  [RC0402]
C167  100nF  [RC0402]
C168  100nF  [RC0402]
C169  10uF ,6.3V  [C0603-08]
C189  10uF ,6.3V  [C0603-08]
C190  100nF  [RC0402]
E14  HDR1X2  [1X2THHDR]
F2  Resettable PTC, 1.1A Ih, 2.2A It  [FUSE-1206]
F3  Resettable PTC, 1.1A Ih, 2.2A It  [FUSE-1206]
J3  USBConn_typeA  [USB-A-SM]
JP10  Jumper, black, 100mil
L7  TCE1210U  [EMI1012-ESD]
L10  TCE1210U  [EMI1012-ESD]
P17  USB3_OTG_MIcroAB  [MICRO-USB3-AB-RA-SM]
R2  10K/1%  [RC0402]
R43  10K/1%  [RC0402]
R63  10K/1%  [RC0402]
R151  100K  [RC0402]
R152  1K/1%  [RC0402]
R153  0R  [RC0402]
R154  1K/1%  [RC0402]
R171  0R  [RC0402]
R172  100K  [RC0402]
R212  0R  [RC1206]
R213  0R  [RC1206]
R236  0R  [RC0402]
R237  0R  [RC0402]
R238  0R  [RC0402]
R239  10K/1%  [RC0402]
U33  RYC8220-1M  [SO-8-150]
U34  USB2.0 mux  [MO-255U1418E]
sheet 05. Audio
C28  1uF  [RC0402]
C29  220pF  [RC0603]
C30  10uF/10V  [0402]
C31  100nF  [RC0402]
C32  10uF/10V  [0402]
C33  100nF  [RC0402]
C34  100nF  [RC0402]
C35  10uF/10V  [0402]
C36  10uF/10V  [0402]
C37  100nF  [RC0402]
C38  1uF  [RC0402]
C39  1uF  [RC0402]
C40  100uF  [C1206]
C41  100uF  [C1206]
C42  220pF  [RC0603]
C43  220pF  [RC0603]
C44  100nF  [RC0402]
C45  1uF  [RC0402]
C46  33pF  [RC0402]
C47  33pF  [RC0402]
C48  10nF  [RC0402]
C49  10nF  [RC0402]
C50  100pF  [RC0402]
P3  AUDIO JACK 3.5mm  [AJ35-4P-SW-SM]
P4  AUDIO JACK 3.5mm  [AJ35-4P-SW-SM]
P5  AUDIO JACK 3.5mm  [AJ35-4P-SW-SM]
R16  680R  [RC0402]
R17  10K/1%  [RC0402]
R18  47K  [RC0402]
R19  47K  [RC0402]
R20  33R  [RC0402]
R21  5.62K/1%  [RC0402]
R22  5.62K/1%  [RC0402]
R23  0R  [RC0402]
R24  0R  [RC0402]
R25  5.62K/1%  [RC0402]
R26  5.62K/1%  [RC0402]
R27  47K  [RC0402]
R28  0R  [RC0402]
R29  0R  [RC0402]
R30  0R  [RC0402]
R31  10K  [RC0402]
R32  100R  [RC0402]
R33  100R/1%  [RC0402]
R34  100R/1%  [RC0402]
R35  220R  [RC0402]
S1  iMX8_SHORT_SMT  [iMX8_SHORT_SMT]
U10  WM8731/L  [MO-220VHHD-1]
X1  12.000 MHZ  [OSC3225]
sheet 06. JTAG, CSI, GPIO expander
C72  100nF  [RC0402]
C73  100nF  [RC0402]
C74  100nF  [RC0402]
C75  100nF  [RC0402]
C76  100nF  [RC0402]
C77  1uF  [RC0402]
C78  100nF  [RC0402]
C79  1uF  [RC0402]
C80  100nF  [RC0402]
C81  100nF  [RC0402]
C192  100nF  [RC0402]
C193  100nF  [RC0402]
D10  BAT54WS  [SOD-323]
OSC1  25.000MHz  [OSC3225]
P7  DR10  [2X5THHDR]
P8  Conn 2x12 B2B P:0.4mm Socket  [B2B04M2X12R]
P10  DR10SM  [2X5SMHDR]
P20  DR34SM  [2X17SMHDR]
P21  DR34SM  [2X17SMHDR]
Q1  NDS335N  [SOT23]
R51  0R  [RC0402]
R52  0R  [RC0402]
R53  10K/1%  [RC0402]
R54  2.2K  [RC0402]
R55  10K/1%  [RC0402]
R56  2.2K  [RC0402]
R57  1K/1%  [RC0402]
R58  10K/1%  [RC0402]
R59  10K/1%  [RC0402]
R60  1K/1%  [RC0402]
R61  0R  [RC0402]
R62  100K  [RC0402]
R64  0R  [RC0402]
R65  0R  [RC0402]
R66  1K/1%  [RC0402]
R67  0R  [RC0402]
R68  0R  [RC0402]
R69  10K/1%  [RC0402]
R70  0R  [RC0402]
R155  0R  [RC0402]
R156  0R  [RC0402]
R157  0R  [RC0402]
R158  0R  [RC0402]
R159  0R  [RC0402]
R160  4.75K/1%  [RC0402]
R162  0R  [RC0402]
R166  0R  [RC0402]
R167  0R  [RC0402]
R174  0R  [RC0402]
R177  0R  [RC0402]
R178  0R  [RC0402]
R179  0R  [RC0402]
R181  0R  [RC0402]
R188  4.75K/1%  [RC0402]
R189  4.75K/1%  [RC0402]
R190  4.75K/1%  [RC0402]
R191  10K/1%  [RC0402]
R193  10K/1%  [RC0402]
R196  0R  [RC0402]
R198  0R  [RC0402]
R200  0R  [RC0402]
R201  0R  [RC0402]
R202  0R  [RC0402]
R203  0R  [RC0402]
R204  0R  [RC0402]
R205  0R  [RC0402]
R234  0R  [RC0402]
R235  10K/1%  [RC0402]
RN17  10K/8P4R  [RESNET8P0805]
U14  TXS0102  [MO-187DA-8]
U35  PCA9555  [QFN4x4-24]
sheet 07. MIPI LCD
C51  100nF  [RC0402]
C52  22uF ,6.3V  [RC0603]
C53  100nF  [RC0402]
C54  100nF  [RC0402]
C185  1uF  [RC0402]
C186  100nF  [RC0402]
C187  1uF  [RC0402]
C188  1uF  [RC0402]
C194  1uF  [RC0402]
C195  10uF ,6.3V,0603  [C0603-08]
C278  1uF, 50V  [RC0603]
D2  BAT54WS  [SOD-323]
D7  ZENER 24V  [SOD-123]
L8  DELTA_SI43-100-10uH  [IND4x4x2_5]
L42  TCE1210U  [EMI1012-ESD]
L43  TCE1210U  [EMI1012-ESD]
L44  TCE1210U  [EMI1012-ESD]
L45  TCE1210U  [EMI1012-ESD]
L46  TCE1210U  [EMI1012-ESD]
P22  FPC_Connector_30  [FPC_30]
P45  FPC_Connector_8  [FPC_8]
R36  0R  [RC0402]
R39  6.2R  [RC0402]
R41  0R  [RC0402]
R75  2.2K  [RC0402]
R82  0R  [RC0402]
R83  0R  [RC0402]
R138  0R  [RC0402]
R139  10K/1%  [RC0402]
R146  0R  [RC0402]
R147  10K/1%  [RC0402]
R173  13.3K  [RC0402]
R176  0R  [RC0402]
R180  0R  [RC0402]
R207  0R  [RC0402]
R208  0R  [RC0402]
R210  0R  [RC0402]
R211  0R  [RC0402]
R215  0R  [RC0402]
R216  0R  [RC0402]
R217  0R  [RC0402]
R218  0R  [RC0402]
R219  0R  [RC0402]
R220  0R  [RC0402]
R221  0R  [RC0402]
R224  10K/1%  [RC0402]
R229  10K/1%  [RC0402]
TP3  TESTPOINT  [TESTPOINT]
U15  YB9285  [SOT23-6L]
U32  IP4220CZ6  [SOT23-6L]
U36  RT9186A  [DFN3x3-8]
sheet 12. ALT boot
C21  100nF  [RC0402]
C23  1uF  [RC0402]
C24  100nF  [RC0402]
C25  100nF  [RC0402]
C26  100nF  [RC0402]
C127  1uF  [RC0402]
C159  1uF  [RC0402]
C160  1uF  [RC0402]
C170  100nF  [RC0402]
C345  100nF  [RC0402]
C346  1uF  [RC0402]
C347  100nF  [RC0402]
E1  HDR1X2  [1X2THHDR]
E2  JP3  [1X3THHDR]
E3  HDR1X2  [1X2THHDR]
E10  HDR1X2  [1X2THHDR]
E12  JP3  [1X3THHDR]
E15  HDR1X2  [1X2THHDR]
JP7  Jumper, black, 100mil
JP9  Jumper, black, 100mil
JP12  Jumper, black, 100mil
JP14  Jumper, black, 100mil
JP15  Jumper, black, 100mil
R1  10K/1%  [RC0402]
R4  0R  [RC0402]
R5  0R  [RC0402]
R6  10K/1%  [RC0402]
R7  100K  [RC0402]
R8  10K/1%  [RC0402]
R10  10K/1%  [RC0402]
R11  100k 1%  [RC0402]
R12  10K/1%  [RC0402]
R13  100K  [RC0402]
R14  10K/1%  [RC0402]
R15  10K/1%  [RC0402]
R37  0R  [RC0402]
R38  0R  [RC0402]
R42  0R  [RC0402]
R44  10K/1%  [RC0402]
R45  10K/1%  [RC0402]
R48  10K/1%  [RC0402]
R49  0R  [RC0402]
R50  0R  [RC0402]
R71  0R  [RC0402]
R76  10K/1%  [RC0402]
R163  10K/1%  [RC0402]
R164  0R  [RC0402]
R175  0R  [RC0402]
R197  0R  [RC0402]
R199  0R  [RC0402]
R249  10K/1%  [RC0402]
R250  10K/1%  [RC0402]
R251  10K/1%  [RC0402]
U1  MIC6315-26D2U  [SOT-143]
U2  NC7SZ74  [MO-187CA-8]
U3  Monostable-FF  [MO-187CA-8]
U6  MIC6315-26D2U  [SOT-143]
U8  Monostable-FF  [MO-187CA-8]
U11  74LCX04  [TSSOP-14]  (sections A,B,C,D,E,F)
U40  NC7SZ57  [MO-252UAAD]
U41  NC7SZ57  [MO-252UAAD]

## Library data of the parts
FID1-FID6 = TESTPOINT_2: CLABCONF0: DNP
PCB1 = PCB,_EM-X270_Rev_1_0.1: CLABCONF0: = SB-UCMIMX8; P/N: 188C03252
ZZ1 = PARSER_VERSION_1_1.0: CLABCONF0: DNP
C2 = 100nF,_10V,_X7R,_10%,_0402_5: CLABCONF0: = SB-UCMIMX8; P/N: 151B10400S
C3 = 100nF,_10V,_X7R,_10%,_0402_8: CLABCONF0: = SB-UCMIMX8; P/N: 151B10400S
C5 = 100nF,_10V,_X7R,_10%,_0402_10: CLABCONF0: = SB-UCMIMX8; P/N: 151B10400S
C6 = 100nF,_10V,_X7R,_10%,_0402_12: CLABCONF0: = SB-UCMIMX8; P/N: 151B10400S
C7 = 100nF,_10V,_X7R,_10%,_0402_2: CLABCONF0: = SB-UCMIMX8; P/N: 151B10400S
C8 = 100nF,_10V,_X7R,_10%,_0402_4: CLABCONF0: = SB-UCMIMX8; P/N: 151B10400S
C9 = 100nF,_10V,_X7R,_10%,_0402_6: CLABCONF0: = SB-UCMIMX8; P/N: 151B10400S
C10 = 100nF,_10V,_X7R,_10%,_0402_9: CLABCONF0: = SB-UCMIMX8; P/N: 151B10400S
C11 = 100nF,_10V,_X7R,_10%,_0402: CLABCONF0: = SB-UCMIMX8; P/N: 151B10400S
C12 = 100nF,_10V,_X7R,_10%,_0402_1: CLABCONF0: = SB-UCMIMX8; P/N: 151B10400S
C13 = 100nF,_10V,_X7R,_10%,_0402_7: CLABCONF0: = SB-UCMIMX8; P/N: 151B10400S
C224 = 100nF,_10V,_X7R,_10%,_0402_3: CLABCONF0: = SB-UCMIMX8; P/N: 151B10400S
C225 = 100nF,_10V,_X7R,_10%,_0402_11: CLABCONF0: = SB-UCMIMX8; P/N: 151B10400S
C35 C340 = 10uF_10V_20%_0402_2: CLABCONF0: = SB-UCMIMX8
C36 C341 = 10uF_10V_20%_0402_3: CLABCONF0: = SB-UCMIMX8
C32 C342 = 10uF_10V_20%_0402_1: CLABCONF0: = SB-UCMIMX8
C343 = 10uF_10V_20%_0402_4: CLABCONF0: = SB-UCMIMX8
C30 C344 = 10uF_10V_20%_0402: CLABCONF0: = SB-UCMIMX8
E5 E14 = HDR_1x2_100MIL_TH_JUMPER: CLABCONF0: = SB-UCMIMX8
JP10 JP11 = Jumper,_black,_100mil: CLABCONF0: = SB-UCMIMX8
P1 P2 = Hirose_DF40C-100DP-0.4V: CLABCONF0: = SB-UCMIMX8; P/N: 182K10005S
R182 = 0R,_0402_0_7: CLABCONF0: = SB-UCMIMX8; P/N: 161C00005S
R183 R202 = 0R,_0402_0_5: CLABCONF0: = SB-UCMIMX8; P/N: 161C00005S
R184 R200 = 0R,_0402_0_1: CLABCONF0: = SB-UCMIMX8; P/N: 161C00005S
R185 = 0R,_0402_0: CLABCONF0: = SB-UCMIMX8; P/N: 161C00005S
R186 R203 = 0R,_0402_0_6: CLABCONF0: = SB-UCMIMX8; P/N: 161C00005S
R187 R234 = 0R,_0402_0_4: CLABCONF0: = SB-UCMIMX8; P/N: 161C00005S
R194 = 0R,_0402_0_2: CLABCONF0: = SB-UCMIMX8; P/N: 161C00005S
R195 = 0R,_0402_0_3: CLABCONF0: = SB-UCMIMX8; P/N: 161C00005S
SW5-SW7 = TACT_SW_6x6mm_SMT: CLABCONF0: = SB-UCMIMX8
TP1-TP9 = TESTPOINT: CLABCONF0: DNP
C60 = Cap.,10uF,6.3V,0603,X5R: CLABCONF0: = SB-UCMIMX8
C61 C167 = 100nF,_10V,_X7R,_10%,_0402_1: CLABCONF0: = SB-UCMIMX8; Group: LAN2
C66 = 100nF,_10V,_X7R,_10%,_0402: CLABCONF0: = SB-UCMIMX8; Group: LAN2
C69 = 1nF,_2KV,SMD_1812,_X7R,_10%: CLABCONF0: = SB-UCMIMX8
D1 = BAT54C: CLABCONF0: = SB-UCMIMX8
FB1 = Ferrite_bead_,_120_Ohm@3A: CLABCONF0: = SB-UCMIMX8
P6 = Con_0.,1GBit_RJ45,_short: CLABCONF0: = SB-UCMIMX8
R40 R180 = 0R,_0402_1: CLABCONF0: DNP
R46 = 475R_1%,_0402_1: CLABCONF0: = SB-UCMIMX8
R47 = 475R_1%,_0402: CLABCONF0: = SB-UCMIMX8
C164 C169 C189 C195 = 10uF,6_0.3V,0603,20%X5R: CLABCONF0: = SB-UCMIMX8
C44 C53 C165 C193 = 100nF,_10V,_X7R,_10%,_0402_3: CLABCONF0: = SB-UCMIMX8
C28 C38 C39 C45 C77 C166 C185 C187 C188 C194 = 1uF,X5R,6.3V,0402: CLABCONF0: = SB-UCMIMX8
C33 C74 C168 C186 = 100nF,_10V,_X7R,_10%,_0402: CLABCONF0: = SB-UCMIMX8
C37 C51 C76 C190 = 100nF,_10V,_X7R,_10%,_0402_2: CLABCONF0: = SB-UCMIMX8
F2 F3 = Fuse,_0.75A_Ih,_1.5A_It: CLABCONF0: = SB-UCMIMX8; P/N: 175P22200S
J3 = USB_Conn.,_Fem,_Type_A_,_TH,_RA: CLABCONF0: = SB-UCMIMX8
L7 L10 L42-L46 = ESD_CHOKE_DIFFx2_10: CLABCONF0: = SB-UCMIMX8; P/N: 142D11801S
P17 = USB3_OTGMINIB_5: CLABCONF0: = SB-UCMIMX8; P/N: 180K01000S
R2 R235 = 10K,1%,0402,1_16W_0_2: CLABCONF0: = SB-UCMIMX8
R43 = 10K,1%,0402,1_16W_0_3: CLABCONF0: = SB-UCMIMX8
R63 = 10K,1%,0402,1_16W_0_1: CLABCONF0: DNP
R62 R151 = 100K,_0402: CLABCONF0: = SB-UCMIMX8; P/N: 161C10031S
R152 = 1K,1%,0402,1_16W: CLABCONF0: = SB-UCMIMX8; Group: CAN
R146 R153 R179 = 0R,_0402_1_2: CLABCONF0: = SB-UCMIMX8
R57 R154 = 1K,1%,0402,1_16W_1: CLABCONF0: = SB-UCMIMX8; Group: CAN
R29 R51 R171 R216 = 0R,_0402_1: CLABCONF0: = SB-UCMIMX8
R172 = 100K,_0402_1: CLABCONF0: = SB-UCMIMX8; P/N: 161C10031S
R212 = 0R,_1206: CLABCONF0: = SB-UCMIMX8
R213 = 0R,_1206_1: CLABCONF0: DNP
R65 R236 = 0R,_0402_1_3: CLABCONF0: = SB-UCMIMX8
R196 R237 = 0R,_0402_1_4: CLABCONF0: = SB-UCMIMX8
R30 R157 R238 = 0R,_0402_1_1: CLABCONF0: = SB-UCMIMX8
R229 R239 = 10K,1%,0402,1_16W_0: CLABCONF0: = SB-UCMIMX8
U33 = RYC8220-1M_DUAL_USB_PWR_SWITCH: CLABCONF0: = SB-UCMIMX8
U34 = USB2_0.0_mux: CLABCONF0: = SB-UCMIMX8; P/N: 116A72220S
C29 = 220pF,50V,NPO,0603_2: CLABCONF0: = SB-UCMIMX8
C31 C78 = 100nF,_10V,_X7R,_10%,_0402_4: CLABCONF0: = SB-UCMIMX8
C34 C54 C75 = 100nF,_10V,_X7R,_10%,_0402_1: CLABCONF0: = SB-UCMIMX8
C40 C41 = 100uF,_6.3V,_X5R,_20%,_1210: CLABCONF0: = SB-UCMIMX8; P/N: 151B10730S
C42 = 220pF,50V,NPO,0603_1: CLABCONF0: = SB-UCMIMX8
C43 = 220pF,50V,NPO,0603: CLABCONF0: = SB-UCMIMX8
C46 C47 = 33pF,50V,NPO,10%,0402_0: CLABCONF0: DNP
C48 = 10nF,_25V,_X7R,_10%,_0402_1: CLABCONF0: = SB-UCMIMX8
C49 = 10nF,_25V,_X7R,_10%,_0402: CLABCONF0: = SB-UCMIMX8
C50 = 100pF,_50V,_NPO,_5%,_0402: CLABCONF0: = SB-UCMIMX8
P3-P5 = Audio_JACK,_STEREO+AUX+SW_3.5mm: CLABCONF0: = SB-UCMIMX8
R16 = 47K,_0402_1: CLABCONF0: = SB-UCMIMX8; P/N: 161C68001S
R17 R147 = 10K,1%,0402,1_16W_1: CLABCONF0: = SB-UCMIMX8
R18 = 47K,_0402: CLABCONF0: = SB-UCMIMX8
R19 = 47K,_0402_2: CLABCONF0: = SB-UCMIMX8
R20 = 33R,5%,0402,1_16W_0: CLABCONF0: = SB-UCMIMX8
R21 = 5.62K_1%,0402_3: CLABCONF0: = SB-UCMIMX8
R22 = 5.62K_1%,0402_1: CLABCONF0: = SB-UCMIMX8
R23 = 0R,_0402_0_2: CLABCONF0: = SB-UCMIMX8
R24 = 0R,_0402_0: CLABCONF0: DNP
R25 = 5.62K_1%,0402: CLABCONF0: = SB-UCMIMX8
R26 = 5.62K_1%,0402_2: CLABCONF0: = SB-UCMIMX8
R27 = 47K,_0402_3: CLABCONF0: = SB-UCMIMX8
R28 = 0R,_0402_0_1: CLABCONF0: = SB-UCMIMX8
R31 = 10K,1%,0402,1_16W: CLABCONF0: = SB-UCMIMX8
R32 = 100R,1%,0402,1_16W_1: CLABCONF0: = SB-UCMIMX8
R33 = 100R,1%,0402,1_16W_2: CLABCONF0: = SB-UCMIMX8
R34 = 100R,1%,0402,1_16W: CLABCONF0: = SB-UCMIMX8
R35 = 220R,5%,0402,1_16W: CLABCONF0: = SB-UCMIMX8
S1 = MISC_SHORT_NL: CLABCONF0: DNP; P/N: iMX8_SHORT
U10 = TSC2046_2: CLABCONF0: = SB-UCMIMX8; P/N: 117A10010S
X1 = TMP_0: CLABCONF0: DNP; P/N: 141B12604I
C72 = 100nF,_10V,_X7R,_10%,_0402_5: CLABCONF0: = SB-UCMIMX8
C73 = 100nF,_10V,_X7R,_10%,_0402_8: CLABCONF0: = SB-UCMIMX8
C79 C127 C159 C160 = 1uF,X5R,6.3V,0402: CLABCONF0: DNP
C80 = 100nF,_10V,_X7R,_10%,_0402_7: CLABCONF0: = SB-UCMIMX8
C81 = 100nF,_10V,_X7R,_10%,_0402_9: CLABCONF0: = SB-UCMIMX8
C192 = 100nF,_10V,_X7R,_10%,_0402_6: CLABCONF0: = SB-UCMIMX8
D2 D10 = BAT54WS_0: CLABCONF0: = SB-UCMIMX8
OSC1 = Osc.,_50Mhz,50PPM,_3.3V: CLABCONF0: = SB-UCMIMX8; P/N: 141C25601S
P7 = HDR_2x5_100MIL_TH: CLABCONF0: = SB-UCMIMX8; Group: COM2
P8 = Conn_2x12_B2B_P_0.4mm_Socket: CLABCONF0: = SB-UCMIMX8; P/N: 182K02401S
P10 = HDR_2x5_100MIL_SMT: CLABCONF0: = SB-UCMIMX8
P20 P21 = HDR_2x17_100MIL_SMT: CLABCONF0: = SB-UCMIMX8
Q1 = N-MOSFET,NDS335N,100mOhm@2.5V: CLABCONF0: = SB-UCMIMX8
R52 = 0R,_0402_1_19: CLABCONF0: DNP
R53 R224 = 10K,1%,0402,1_16W: CLABCONF0: DNP
R54 R75 = 2.2K,5%,0402.1_16W: CLABCONF0: = SB-UCMIMX8
R55 = 10K,1%,0402,1_16W_1: CLABCONF0: DNP
R56 = 2.2K,5%,0402.1_16W_1: CLABCONF0: = SB-UCMIMX8
R58 = 10K,1%,0402,1_16W_3: CLABCONF0: = SB-UCMIMX8
R59 = 10K,1%,0402,1_16W_4: CLABCONF0: DNP
R60 = 1K,1%,0402,1_16W_2: CLABCONF0: = SB-UCMIMX8; Group: CAN
R61 = 0R,_0402_1_14: CLABCONF0: = SB-UCMIMX8
R64 = 0R,_0402_1_13: CLABCONF0: = SB-UCMIMX8
R66 = 1K,1%,0402,1_16W: CLABCONF0: DNP; Group: CAN
R67 = 0R,_0402_1_17: CLABCONF0: DNP
R68 = 0R,_0402_1_21: CLABCONF0: = SB-UCMIMX8
R69 = 10K,1%,0402,1_16W_2: CLABCONF0: DNP
R70 = 0R,_0402_1_6: CLABCONF0: DNP
R155 = 0R,_0402_1_9: CLABCONF0: DNP
R156 = 0R,_0402_1_15: CLABCONF0: = SB-UCMIMX8
R158 = 0R,_0402_1_7: CLABCONF0: = SB-UCMIMX8
R159 = 0R,_0402_1_10: CLABCONF0: DNP
R160 = 4_0.75K,1%,0402,1_16W: CLABCONF0: = SB-UCMIMX8
R162 = 0R,_0402_1_11: CLABCONF0: DNP
R166 = 0R,_0402_1_22: CLABCONF0: DNP
R167 = 0R,_0402_1_20: CLABCONF0: DNP
R174 = 0R,_0402_1_12: CLABCONF0: = SB-UCMIMX8
R177 = 0R,_0402_1_16: CLABCONF0: = SB-UCMIMX8
R178 = 0R,_0402_1_5: CLABCONF0: = SB-UCMIMX8
R181 = 0R,_0402_1_18: CLABCONF0: = SB-UCMIMX8
R188 = 4_0.75K,1%,0402,1_16W_1: CLABCONF0: = SB-UCMIMX8
R189 = 4_0.75K,1%,0402,1_16W_2: CLABCONF0: = SB-UCMIMX8
R190 = 4_0.75K,1%,0402,1_16W_3: CLABCONF0: = SB-UCMIMX8
R191 = 10K,1%,0402,1_16W_0_1: CLABCONF0: = SB-UCMIMX8
R193 R251 = 10K,1%,0402,1_16W_0: CLABCONF0: DNP
R198 = 0R,_0402_1_8: CLABCONF0: = SB-UCMIMX8
R42 R201 = 0R,_0402_0_3: CLABCONF0: DNP; P/N: 161C00005S
R38 R204 R207 = 0R,_0402_0: CLABCONF0: DNP; P/N: 161C00005S
R205 = 0R,_0402_0_2: CLABCONF0: DNP; P/N: 161C00005S
RN17 = RN,10K,8P4R@0805: CLABCONF0: = SB-UCMIMX8
U14 = TXS0102_0: CLABCONF0: = SB-UCMIMX8; P/N: 116A01020S
U35 = PCA9555: CLABCONF0: = SB-UCMIMX8
C52 = 22uF,6.3V,X5R: CLABCONF0: = SB-UCMIMX8; P/N: 151B22610S
C278 = 1uF,X5R,6.3V,0402: CLABCONF0: = SB-UCMIMX8; P/N: 151D10510S
D7 = ZENER_24V_500mW_SOD-123: CLABCONF0: DNP
L8 = INC_DELTA_SI43-100,_10uH: CLABCONF0: = SB-UCMIMX8; CLABCONF1: <null>; CLABCONF2: <null>; CLABCONF3: <null>; CLABCONF4: <null>; CLABCONF5: <null>; CLABCONF6: <null>; CLABCONF7: <null>; CLABCONF8: <null>; CLABCONF9: <null>
P22 = FPC_Connector_30: CLABCONF0: = SB-UCMIMX8; P/N: 182P03002S
P45 = FPC_Connector_8: CLABCONF0: = SB-UCMIMX8; P/N: 182P00802S
R36 = 2.2R,5%,0402,1_16W_1: CLABCONF0: = SB-UCMIMX8; P/N: 161C00005S
R39 = 2.2R,5%,0402,1_16W: CLABCONF0: = SB-UCMIMX8; P/N: 161C06R25S
R41 = 0R,_0402_3: CLABCONF0: = SB-UCMIMX8
R82 = 0R,_0402_8: CLABCONF0: DNP
R83 = 0R,_0402_7: CLABCONF0: = SB-UCMIMX8
R138 = 0R,_0402_11: CLABCONF0: = SB-UCMIMX8
R139 = 10K,1%,0402,1_16W_2: CLABCONF0: = SB-UCMIMX8
R173 = 13.3K,_0402_tmp: CLABCONF0: = SB-UCMIMX8; P/N: 161C13321S
R176 = 0R,_0402_1_1: CLABCONF0: DNP
R208 = 0R,_0402: CLABCONF0: = SB-UCMIMX8
R210 = 0R,_0402_5: CLABCONF0: DNP
R211 = 0R,_0402_6: CLABCONF0: = SB-UCMIMX8
R215 = 0R,_0402_0_1: CLABCONF0: DNP; P/N: 161C00005S
R217 = 0R,_0402_12: CLABCONF0: = SB-UCMIMX8
R218 = 0R,_0402_9: CLABCONF0: = SB-UCMIMX8
R219 = 0R,_0402_4: CLABCONF0: = SB-UCMIMX8
R220 = 0R,_0402_2: CLABCONF0: = SB-UCMIMX8
R221 = 0R,_0402_10: CLABCONF0: = SB-UCMIMX8
U15 = AIC1647_0: CLABCONF0: = SB-UCMIMX8; P/N: 123C40000S
U32 = IP4220CZ6_0: CLABCONF0: = SB-UCMIMX8
U36 = RT9186A,LDO_,2.5-5_0.5V,500mA: CLABCONF0: = SB-UCMIMX8
C21 = 100nF,_10V,_X7R,_10%,_0402_4: CLABCONF0: =ATP
C23 C346 = 1uF,X5R,6.3V,0402: CLABCONF0: =ATP
C24 = 100nF,_10V,_X7R,_10%,_0402_6: CLABCONF0: =ATP
C25 = 100nF,_10V,_X7R,_10%,_0402_2: CLABCONF0: =ATP
C26 = 100nF,_10V,_X7R,_10%,_0402: CLABCONF0: =ATP
C170 = 100nF,_10V,_X7R,_10%,_0402_5: CLABCONF0: =ATP
C345 = 100nF,_10V,_X7R,_10%,_0402_3: CLABCONF0: =ATP
C347 = 100nF,_10V,_X7R,_10%,_0402_1: CLABCONF0: =ATP
E1 = HDR_1x2_100MIL_TH_JUMPER_3: CLABCONF0: =ATP
E2 E12 = HDR_1x3_100MIL_TH_JUMPER: CLABCONF0: =ATP
E3 = HDR_1x2_100MIL_TH_JUMPER_1: CLABCONF0: =ATP
E10 = HDR_1x2_100MIL_TH_JUMPER_2: CLABCONF0: =ATP
E15 = HDR_1x2_100MIL_TH_JUMPER: CLABCONF0: =ATP
JP7 JP9 JP12 JP14 JP15 = Jumper,_black,_100mil: CLABCONF0: =ATP
R1 = 10K,1%,0402,1_16W_0_9: CLABCONF0: =ATP
R4 = 0R,_0402_0_5: CLABCONF0: =ATP; P/N: 161C00005S
R5 = 0R,_0402_0_7: CLABCONF0: =ATP; P/N: 161C00005S
R6 = 10K,1%,0402,1_16W_0_1: CLABCONF0: =ATP
R7 = 100K,_0402_1: CLABCONF0: =ATP; P/N: 161C10031S
R8 = 10K,1%,0402,1_16W_0_13: CLABCONF0: =ATP
R10 = 10K,1%,0402,1_16W_0_3: CLABCONF0: DNP
R11 = 100k,_%1,_0402: CLABCONF0: =ATP
R12 = 10K,1%,0402,1_16W_0_2: CLABCONF0: =ATP
R13 = 100K,_0402: CLABCONF0: =ATP; P/N: 161C10031S
R14 = 10K,1%,0402,1_16W_0_14: CLABCONF0: =ATP
R15 = 10K,1%,0402,1_16W_0_7: CLABCONF0: =ATP
R37 = 0R,_0402_0_10: CLABCONF0: DNP; P/N: 161C00005S
R44 = 10K,1%,0402,1_16W_0_6: CLABCONF0: =ATP
R45 = 10K,1%,0402,1_16W_0_4: CLABCONF0: =ATP
R48 = 10K,1%,0402,1_16W_0_12: CLABCONF0: =ATP
R49 = 0R,_0402_0_8: CLABCONF0: DNP; P/N: 161C00005S
R50 = 0R,_0402_0_6: CLABCONF0: =ATP; P/N: 161C00005S
R71 = 0R,_0402_0_4: CLABCONF0: =ATP; P/N: 161C00005S
R76 = 10K,1%,0402,1_16W_0_8: CLABCONF0: =ATP
R163 = 10K,1%,0402,1_16W_0_5: CLABCONF0: =ATP
R164 = 0R,_0402_0_9: CLABCONF0: =ATP; P/N: 161C00005S
R175 = 0R,_0402_0_1: CLABCONF0: =ATP; P/N: 161C00005S
R197 = 0R,_0402_0_11: CLABCONF0: =ATP; P/N: 161C00005S
R199 = 0R,_0402_0_2: CLABCONF0: =ATP; P/N: 161C00005S
R249 = 10K,1%,0402,1_16W_0_10: CLABCONF0: =ATP
R250 = 10K,1%,0402,1_16W_0_11: CLABCONF0: DNP
U1 = ADM6315_RESET_1: CLABCONF0: =ATP; P/N: 117A63150S
U2 = NC7SZ74_D-Type_Flip-Flop: CLABCONF0: =ATP; P/N: 106F20740S
U3 U8 = Monostable-FF: CLABCONF0: =ATP; P/N: 106H20000S
U6 = ADM6315_RESET_1: CLABCONF0: =ATP; P/N: 117A63151S
U11 = 74LCX04_sgl_gate_TSSOP-14: CLABCONF0: = SB-UCMIMX8
U40 U41 = MicroGate_NC7SZ57,Univ_Gate: CLABCONF0: =ATP; P/N: 106C20570S

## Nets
3V3_AW: C21.1 C24.1 C25.2 C26.1 C170.1 C193.1 C345.1 C347.1 P10.1 P20.7 P20.13 R1.2 R7.2 R8.2 R11.2 R13.2 R14.2 R43.2 R48.2 R63.2 R71.1 R76.1 R151.2 R159.2 R160.1 R166.2 R167.2 R182.1 R188.1 R193.1 R201.2 R235.1 R249.2 R250.2 R251.2 U1.4(VCC) U2.8(VCC) U3.8(VCC) U6.4(VCC) U8.8(VCC) U11.14(VCC) U35.21(VDD) U40.5(VCC) U41.5(VCC) ; also on sheet 10 11 12
3V3_PER: C30.1 C31.1 C32.1 C33.1 C34.1 C35.1 C36.1 C37.1 C72.1 C167.2 C185.1 C192.2 P7.2 R64.1 R83.2 R138.1 R172.2 R200.2 R210.1 R216.1 U10.3(DCVDD) U10.5(DBVDD) U10.12(HPVDD) U10.18(AVDD) U14.7(VCCB) U34.9(VCC) ; also on sheet 9 10 12
5V0_PER: C189.1 C190.1 P20.6 R212.1 U33.7(VCC) ; also on sheet 10
5V0_USB2: F3.2 R212.2 R213.1
AGND: C34.2 C35.2 C36.2 C37.2 C42.2 C43.2 C44.2 C45.2 R19.2 R25.1 R26.1 R27.2 R29.2 S1.2 U10.15(HPGND) U10.19(AGND) U10.29(PAD) ; also on sheet 12
AVDD33_ETH: C225.2 C343.2 P1.62 R40.2
GND: C2.2 C3.2 C5.2 C6.2 C7.2 C8.2 C9.2 C10.2 C11.2 C12.2 C13.2 C21.2 C24.2 C25.1 C26.2 C30.2 C31.2 C32.2 C33.2 C46.1 C47.1 C51.2 C52.2 C53.2 C54.1 C60.2 C61.2 C66.2 C69.2 C72.2 C73.2 C74.1 C75.2 C76.2 C77.2 C78.2 C79.1 C80.1 C81.2 C127.1 C159.1 C160.1 C164.2 C165.2 C166.2 C167.1 C168.2 C169.2 C170.2 C185.2 C186.2 C187.1 C188.2 C189.2 C190.2 C192.1 C193.2 C194.2 C195.2 C224.2 C225.1 C278.2 C340.2 C341.2 C342.2 C343.1 C344.2 C345.2 C347.2 E1.2 E2.3 E14.1 FB1.2 J3.4(GND) J3.5(SHELL_1) J3.6(SHELL_2) L7.5(GND) L7.6(GND) L10.5(GND) L10.6(GND) L42.5(GND) L42.6(GND) L43.5(GND) L43.6(GND) L44.5(GND) L44.6(GND) L45.5(GND) L45.6(GND) L46.5(GND) L46.6(GND) OSC1.2(GND) P1.10 P1.20 P1.40 P1.54 P1.64 P1.78 P1.88 P2.10 P2.16 P2.22 P2.28 P2.34 P2.40 P2.46 P2.54 P2.72 P2.82 P7.4 P7.6 P8.2(AGND) P8.15(DGND) P8.24(AF_GND) P10.10 P17.5(GND) P17.8(GNDD) P17.NC1(CHASSIS) P17.NC2(CHASSIS) P17.NC3(CHASSIS) P17.NC4(CHASSIS) P17.NC5(CHASSIS) P17.NC6(CHASSIS) P20.31 P20.32 P21.6 P21.9 P22.6 P22.9 P22.12 P22.15 P22.18 P22.21 P22.22 P22.24 P22.29 P22.30 Q1.2(S) R5.2 R6.1 R10.1 R12.1 R15.1 R30.1 R36.2 R44.2 R45.2 R46.2 R47.2 R51.1 R55.1 R57.1 R60.1 R66.1 R69.1 R75.2 R139.2 R163.2 R183.2 R184.2 R191.2 R194.2 R199.2 R219.1 R239.1 RN17.2(RB1) RN17.3(RC1) RN17.4(RD1) S1.1 U1.1(GND) U2.4(GND) U3.4(GND) U6.1(GND) U8.4(GND) U10.4(DGND) U10.25(MODE) U10.26(CSB) U11.7(GND) U14.2(GND) U15.2(GND) U33.6(GND) U34.4(GND) U35.9(VSS) U36.5(GND) U36.9(EPAD) U40.2(GND) U41.2(GND) X1.2 X1.4 ; also on sheet 9 10 11 12
VBUS1_FUSED: C164.1 F2.1 P17.1(5VUSB) R152.2
VBUS_OTG: C165.1 C166.1 F2.2 U33.8(OUT_A)
VBUS_USB2: R213.2 U33.5(OUT_B)
VCC_RTC: P1.93 ; also on sheet 10
A_IN: C48.2 R32.2
A_LOW: R6.2 U3.1(A)
ADCLRC: R23.1 R24.1 U10.11(ADCLRC)
ADV_OS_H: E3.1 U8.5(Q)
ADV_RES_A: R164.2 U40.4(Y)
ADV_RES_B: R163.1 R164.1 U41.1(I1)
ADV_RES_L: R11.1 U6.3(~{MR}) U41.4(Y)
ALT_BOOT: E10.2 E15.2 P1.90 R37.1 R186.1
ALT_BOOT_INV: R175.2 U2.3(\\Q)
ALT_BOOT_INV_DEL: C127.2 R175.1 U8.2(B)
ALT_RES: R4.2 R250.1 U1.2(~{RESET})
AMP_IN: R31.2 R32.1 U11.3(I)
AMP_OUT: R31.1 U11.1(I) U11.4(12)
AMPR: C28.2 R17.1
ATP_ALT_BOOT: E10.1 R37.2 U2.5(Q)
ATP_RESL: E12.3 R38.2 R251.1 U6.2(~{RESET})
AUD_VMID: C44.1 C45.1 U10.20(VMID)
AUDIO_IN_DIG: C48.1 P4.2(AUX) R34.2
AUDIO_OUT_DIG: C50.1 P5.2(AUX) R33.2 R35.1
BCKLIGHT_FB: D7.2(ANODE) R41.2 U15.3(FB)
CAM_SCCB_EN: C77.1 R58.2 U14.6(OE)
CARRER_I2C_SDA_1V8: P8.3(SDA) R54.1 U14.5(A1)
CARRIER_3V3_GPIO0_0: R156.2 U35.1(I/O0.0)
CARRIER_3V3_GPIO0_1: R157.2 U35.2(I/O0.1)
CARRIER_3V3_GPIO0_2: R158.2 U35.3(I/O0.2)
CARRIER_3V3_GPIO0_3: R174.2 U35.4(I/O0.3)
CARRIER_3V3_GPIO0_4: R196.2 U35.5(I/O0.4)
CARRIER_3V3_GPIO0_5: R176.2 U35.6(I/O0.5)
CARRIER_3V3_GPIO0_6: R177.2 U35.7(I/O0.6)
CARRIER_3V3_GPIO0_7: R180.2 U35.8(I/O0.7)
CARRIER_3V3_GPIO1_0: R178.2 U35.10(I/O1.0)
CARRIER_3V3_GPIO1_1: R179.2 U35.11(I/O1.1)
CARRIER_3V3_GPIO1_2: R181.2 U35.12(I/O1.2)
CARRIER_3V3_GPIO1_3: R198.2 U35.13(I/O1.3)
CARRIER_I2C_SCL_1V8: P8.5(SCL) R56.1 U14.4(A2)
CDC_BCLK: R20.2 U10.7(BCLK)
CLR_H: C159.2 R8.1 U3.3(CLR)
CODEC_XTALIN: C46.2 R28.1 U10.1(XTI/MCLK) X1.1(Y1)
CODEC_XTALOUT: C47.2 U10.2(XTO) X1.3(Y3)
CONN_AGND: C29.1 C50.2 P3.1(COM) P4.1(COM) P5.1(COM) R18.2 R29.1 R30.2 R34.1 R35.2
CONN_CAM_CLK: P8.13(XCLK) R65.1 R66.2
CSI_P1_CKN: P2.2 P8.18(MCN)
CSI_P1_CKP: P2.4 P8.16(MCP)
CSI_P1_DN0: P2.6 P8.22(MDN0)
CSI_P1_DN1: P2.31 P8.14(MDN1)
CSI_P1_DN2: P2.25 P21.1
CSI_P1_DN3: P2.35 P21.5
CSI_P1_DP0: P2.8 P8.20(MDP0)
CSI_P1_DP1: P2.33 P8.12(MDP1)
CSI_P1_DP2: P2.27 P21.3
CSI_P1_DP3: P2.37 P21.7
CSI_PWR_DWN: P8.8(PWDN) Q1.3(D) R59.1 R60.2 R178.1
CSI_RST: P8.6(RESET) R57.2 R174.1
CSTRB: P8.1(STROBE) R53.2 R55.2
DBG_UART_RXD: P1.76 ; also on sheet 11
DBG_UART_TXD: P1.74 ; also on sheet 11
DEBUGSEL: R158.1 ; also on sheet 11
DISP_IO: C54.2 C188.1 P22.27 R82.2 R83.1
DISP_PWRA: C53.1 C187.2 P22.28 R138.2
DISP_RESET: P22.26 R75.1 R177.1 R215.1
DS2_CON_DN: J3.2(D-) L10.2
DS2_CON_DP: J3.3(D+) L10.1
DSI_1V8: C195.1 R82.1 R147.1 R173.2 U36.7(Vout1) U36.8(Vout2)
DSI_1V8_EN: R146.1 R224.2 U36.4(EN)
DSI_1V8_PGOOD: R147.2 U36.3(PGOOD)
DSI_CKN: L44.3 P2.21
DSI_CKP: L44.4 P2.23
DSI_CN: L44.2 P22.13
DSI_CP: L44.1 P22.14
DSI_DN0: L42.3 P2.1
DSI_DN1: L43.3 P2.15
DSI_DN2: L45.3 P2.5
DSI_DN3: L46.3 P2.11
DSI_DP0: L42.4 P2.3
DSI_DP1: L43.4 P2.17
DSI_DP2: L45.4 P2.7
DSI_DP3: L46.4 P2.13
DSI_LDO_1V8: R139.1 R173.1 U36.6(ADJ)
DSI_N0: L42.2 P22.7
DSI_N1: L43.2 P22.10
DSI_N2: L45.2 P22.16
DSI_N3: L46.2 P22.19
DSI_P0: L42.1 P22.8
DSI_P1: L43.1 P22.11
DSI_P2: L45.1 P22.17
DSI_P3: L46.1 P22.20
ECSPI1_MISO: P1.44 P21.34
ECSPI1_MOSI: P1.42 P21.32
ECSPI1_SCLK: P1.48 P21.33
ECSPI1_SS0: P1.46 P21.30
ECSPI2_MISO/UART4_CTS_B_CM: P2.89 P21.22
ECSPI2_MOSI/UART4_TX_CM: P2.95 P21.28
ECSPI2_SCLK/UART4_RX_CM: P2.93 P21.26
ECSPI2_SS0/UART4_RTS_B_CM: P2.91 P21.24
ENET_MDC_CM: P2.76 TP6.1
ENET_MDIO_CM: P2.88 TP7.1
ENET_TD2_CM: P2.77 TP5.1
ETH0_SHIELD: C69.1 FB1.1 P6.S1(SHIELD) P6.S2(SHIELD)
ETH1_CT1: C60.1 C61.1 P6.P5(CT) R40.1
ETH1_CT2: C66.1 P6.P6(CT)
ETH1_GREEN_LED_CAT: P6.P11(LED1_C) R46.1
ETH1_LED_ACT/PHY1ADDRESS2: P2.83 P6.P12(LED1_A)
ETH1_LINK-LED_10_100: D1.1(ANODE1) P2.86
ETH1_LINK-LED_1000/INTSELECT: D1.2(ANODE2) P2.75
ETH1_MDI0N: P2.73 P6.P2(MDI0-)
ETH1_MDI0P: P2.74 P6.P1(MDI0+)
ETH1_MDI1N: P2.80 P6.P4(MDI1-)
ETH1_MDI1P: P2.78 P6.P3(MDI1+)
ETH1_MDI2N: P2.81 P6.P8(MDI2-)
ETH1_MDI2P: P2.79 P6.P7(MDI2+)
ETH1_MDI3N: P2.85 P6.P10(MDI3-)
ETH1_MDI3P: P2.84 P6.P9(MDI3+)
ETH1_YELLOW_LED_AN: D1.3(CATHODE) P6.P14(LED2_A)
ETH1_YELLOW_LED_CAT: P6.P13(LED2_C) R47.1
EXPANDER_A0: R166.1 RN17.5(RD2) U35.18(A0)
EXPANDER_A1: R167.1 RN17.6(RC2) U35.23(A1)
EXPANDER_A2: R159.1 RN17.7(RB2) U35.24(A2)
FPC_GND: P45.1 P45.8 R219.2 U32.2(GND)
FPC_INT: P45.6 R176.1 R220.2 U32.3(IO2)
FPC_PWR: C186.1 P45.3 R216.2 U32.5(VBUS)
FPC_RES: P45.7 R221.2 U32.1(IO1)
FPC_SCL: P45.4 R218.2 U32.4(IO3)
FPC_SDA: P45.5 R217.2 U32.6(IO4)
GPIO1_I13: P1.60 R211.1
GPIO1_IO8: P1.58 P21.25
GPIO_PHY1_INT: P2.70 TP9.1
GPIO_PHY1_WOL: P2.68 TP8.1
GPIO_USB_ID: P2.90 R171.2
HUB_OE: R239.2 U34.8(\\~{O}E)
I2C1_SCL: P1.100 R160.2 R205.2 U35.19(SCL) ; also on sheet 11
I2C1_SDA: P1.96 R188.2 R204.2 U35.20(SDA) ; also on sheet 11
I2C3_SCL: P1.94 P20.33
I2C3_SDA: P1.91 P20.34
I2C4_SCL: R202.1 R205.1 R218.1 U10.28(SCLK) U14.1(B2) ; also on sheet 9
I2C4_SCL_CM: P1.87 P21.2 R190.2 R202.2
I2C4_SDA: R203.1 R204.1 R217.1 U10.27(SDIN) U14.8(B1) ; also on sheet 9
I2C4_SDA_CM: P1.89 P21.4 R189.2 R203.2
IDT_T_CLK2_N: P10.8 ; also on sheet 9
IDT_T_CLK2_P: P10.6 ; also on sheet 9
INT_EXP: R234.1 R235.2 U35.22(\\~{IN}T)
INT_I2C_EXP: P1.85 R234.2
J_MOD_8: P7.8 R155.2
JTAG_HDR_10: P7.10 R51.2 R52.2
JTAG_MOD: P1.75 R155.1
JTAG_nTRST: P1.63 R52.1
JTAG_RST: D10.CATHODE P7.9 R162.1
JTAG_TCK: P1.73 P7.3
JTAG_TDI: P1.71 P7.7
JTAG_TDO: P1.67 P7.5
JTAG_TMS: P1.65 P7.1
JUMP_RES: E12.1 R199.1
LCDINT_GPIO1_IO1: P1.56 P20.29 R220.1
LED_A: C278.1 D2.CATHODE D7.1(CATHODE) P22.4 U15.5(OVP)
LED_EN: R180.1 R211.2 R229.2 U15.4(EN/PWM)
LED_K: P22.2 R39.1 R41.1
LHPOUT: C41.1 P5.4(L) R19.1
LHPOUT_T: C41.2 U10.13(LHPOUT)
LIN_T: C39.2 C42.1 R22.1 R25.2
LLINEIN: P4.4(L) R22.2
LLINEIN_T: C39.1 U10.24(LLINEIN)
MCLK_VCC: C81.1 OSC1.4(VCC) R64.2 R67.1
MIC_IN: C28.1 C29.2 P3.4(L) R16.2 R18.1
MICBIAS: R16.1 U10.21(MICBIAS)
MICIN: R17.2 U10.22(MICIN)
MIPICAM_DVDD1V5: C78.1 P8.10(DVDD1.5V) R61.1
mPCIe_PERST: R156.1 ; also on sheet 9
MUX_PCI_USB_DN: U34.6(HSD2-) ; also on sheet 9
MUX_PCI_USB_DP: U34.2(HSD2+) ; also on sheet 9
MUX_USB_CON_DN: L10.3 U34.7(HSD1-)
MUX_USB_CON_DP: L10.4 U34.1(HSD1+)
ONESHOT_CEXT: C23.2 U3.6(Cext)
ONESHOT_CEXT_B: C346.2 U8.6(Cext)
ONESHOT_REXT: C23.1 R7.1 U3.7(Rext)
ONESHOT_REXT_B: C346.1 R13.1 U8.7(Rext)
OR_LOW: E3.2 R15.2 U40.3(I0)
OSC25MHZ: OSC1.3(OUT) R65.2
OSCEN: OSC1.1(EN) R68.1 R69.2 R70.1
OTG_DN: L7.2 P17.2(D-)
OTG_DP: L7.1 P17.3(D+)
PB_ALT_BOOT: R42.2 R186.2 SW7.2 SW7.4
PB_RESET: R49.2 R185.2 SW6.2 SW6.4
PBALT_BOOT: R42.1 U1.3(~{MR})
PBRESET: R10.2 R49.1 R76.2 U41.6(I2)
PCIE1_RXN_N: P2.30 ; also on sheet 9
PCIE1_RXN_P: P2.32 ; also on sheet 9
PCIE1_TXN_N: P2.36 ; also on sheet 9
PCIE1_TXN_P: P2.38 ; also on sheet 9
PCIE_EXT_REF_CLKN: P2.44 ; also on sheet 9
PCIE_EXT_REF_CLKP: P2.42 ; also on sheet 9
PCIE_INT_REF_CLKN: P2.26 ; also on sheet 9
PCIE_INT_REF_CLKP: P2.24 ; also on sheet 9
PHY_2V5: C224.1 P1.55 ; also on sheet 10
PIMIC_POWER_ON: E5.1 P1.59 R187.1
PIMICPOWER_ON: E5.2 R194.1
PMIC_ON_REQ: P1.68 P10.5 R146.2 ; also on sheet 10
PMIC_STBY_REQ: P1.66 P10.3
POR_B: D10.ANODE E12.2 P2.66 P10.7 R38.1 R162.2 R185.1 R207.2 R215.2 ; also on sheet 9
PWDN_CAM_DLY: C79.2 Q1.1(G) R62.2
PWR_I2C4: R189.1 R190.1 R200.1 R201.1
PWRBTN: P2.64 R195.1
QSPIA_DATA0: P2.61 P20.22
QSPIA_DATA1: P2.56 P20.21
QSPIA_DATA2: P2.43 P20.10
QSPIA_DATA3: P2.58 P20.23
QSPIA_nSS0: P2.65 P20.26
QSPIA_SCLK: P2.55 P20.18
Res_ ATP: P1.95 R197.2
ResATP: R45.1 R197.1 U40.6(I2)
REVR_PR: P1.47 ; also on sheet 10
RHPOUT: C40.1 P5.3(R) R27.1
RHPOUT_T: C40.2 U10.14(RHPOUT)
RIN_T: C38.2 C43.1 R21.1 R26.2
Rise: E2.1 R4.1 U3.2(B)
RLINEIN: P4.3(R) R21.2
RLINEIN_T: C38.1 U10.23(RLINEIN)
SAI1_MCLK: P2.62 P20.27
SAI1_RXC: P2.69 P20.30
SAI1_RXD0: P2.48 P20.15
SAI1_RXD1: P2.50 P20.17
SAI1_RXD2: P2.52 P20.19
SAI1_RXD3: P2.60 P20.25
SAI1_RXFS: P2.47 P20.14
SAI1_TXC: P2.45 P20.12
SAI1_TXD0: P2.53 P20.16
SAI1_TXD1: P2.59 P20.20
SAI1_TXD2: P2.63 P20.24
SAI1_TXD3: P2.67 P20.28
SAI1_TXFS: P2.41 P20.8
SAI2_MCLK: P1.30 R28.2
SAI2_RXC: P1.32 P21.31
SAI2_RXD: P1.28 U10.10(ADCDAT)
SAI2_RXFS: P1.34 R24.2
SAI2_TXC: P1.36 R20.1
SAI2_TXD: P1.26 U10.8(DACDAT)
SAI2_TXFS: P1.38 R23.2 U10.9(DACLRC)
SAI3_MCLK: P1.17 P21.15
SAI3_RXC: P1.21 P21.19
SAI3_RXD: P1.19 P21.17
SAI3_RXFS: P1.25 P21.23
SAI3_TXC: P1.15 P21.13
SAI3_TXD: P1.13 P21.11
SAI3_TXFS: P1.23 P21.21
SAI5_MCLK: P1.41 P21.18
SAI5_RXC: P1.31 P21.10
SAI5_RXD0: P1.35 P21.14
SAI5_RXD1: P1.33 P21.12
SAI5_RXD2: P1.37 P21.16
SAI5_RXD3: P1.29 P21.8
SAI5_RXFS: P1.39 P21.20
SD2_CLK: P2.96 ; also on sheet 11
SD2_CMD: P2.100 ; also on sheet 11
SD2_DATA0: P2.97 ; also on sheet 11
SD2_DATA1: P2.99 ; also on sheet 11
SD2_DATA2: P2.94 ; also on sheet 11
SD2_DATA3: P2.98 ; also on sheet 11
SD2_nCD: P2.92 ; also on sheet 11
SD2_nRST: P2.51 P21.29
SD2_WP: P2.49 P10.9 R191.1 R193.2
SD_BOOT_DISH: U3.5(Q) U11.11(I)
SD_BOOT_DISL: R50.2 U11.10(12)
SD_BOOT_DISL_R: R50.1 U2.1(CK)
SD_BOOT_EN: E2.2 R249.1 U2.7(\\~{P}R)
SDBOOT: E15.1 R71.2
SPDIF_EXT_CLK: P1.77 P20.5
SPDIF_OUT1C: C49.1 R33.1
SPDIF_RX: P1.79 U11.2(12)
SPDIF_TX: C49.2 P1.81
SW_BOOT: R182.2 SW7.1 SW7.3
SW_PWRBTN: R184.1 SW5.1 SW5.3
SW_RES: R183.1 SW6.1 SW6.3
SWPWRBTN: R187.2 R195.2 SW5.2 SW5.4
SYS_I2C_SCL: P1.99 P10.4
SYS_I2C_SDA: P1.97 P10.2
TOUCH_RESET: R196.1 R207.1 R221.1
TP1: P1.92 TP1.1
TP2: P1.98 TP2.1
TP3: P22.25 TP3.1
TP4: P1.61 TP4.1
U2_D: R5.1 U2.2(D)
U8_A: R12.2 U8.1(A)
U8_CLR: C160.2 R14.1 U8.3(CLR)
U40_I1: R44.1 U40.1(I1)
U41_I0: R48.1 U41.3(I0)
UART1_RXD/ECSPI3_SCLK: P1.70 P20.11 ; also on sheet 11
UART1_TXD/ECSPI3_MOSI: P1.72 P20.9 ; also on sheet 11
UART2_RXD/ECSPI3_MISO: P1.80 P20.3
UART2_TXD/ECSPI3_SS0: P1.82 P20.1
UART4_RXD: P1.84 P20.4 ; also on sheet 11
UART4_TXD: P1.86 P20.2 ; also on sheet 11
USB1_DN: L7.3 P1.14
USB1_DP: L7.4 P1.12
USB1_EN: R63.1 R238.1 U33.1(EN_A)
USB1_ID: P1.22 R153.2
USB1_ID_CONN: R151.1 R153.1 R171.1 R237.2 U11.9(I)
USB1_ID_CONN_R: P17.4(ID) R237.1
USB1_VBUS_DET: P1.24 R152.1
USB1_VBUS_EN: R238.2 U11.8(12)
USB2_DN: P1.5 U34.5(D-)
USB2_DP: P1.3 U34.3(D+)
USB2_HOST_VBUS: C168.1 C169.1 F3.1 J3.1(VBUS) R154.2
USB2_VBUS_DET: P1.1 R154.1
USB2_VBUS_EN: R236.2 U11.6(12)
USB2_VBUS_EN_R: R43.1 R236.1 U33.4(EN_B)
USB_MUX_SEL: E14.2 R2.2 R172.1 U11.5(I) U34.10(SEL)
USBMUX_SEL: R2.1 R157.1
V_LED: C51.1 C52.1 L8.1 R208.2 R210.2 R229.1 U15.6(IN)
V_SOM: C2.1 C3.1 C5.1 C6.1 C7.1 C8.1 C9.1 C10.1 C11.1 C12.1 C13.1 C194.1 C340.1 C341.1 C342.1 C344.1 P1.11 P1.27 P1.43 P1.57 P1.69 P1.83 P2.9 P2.19 P2.29 P2.39 P2.57 P2.71 P2.87 R208.1 R224.1 U36.1(Vin1) U36.2(Vin2) ; also on sheet 10 12
V_SOM_EN: P21.27 ; also on sheet 10
VSB_1V5: R61.2 ; also on sheet 9 10
VSB_1V8: C73.1 C80.2 P8.11(DVDD1.8V/2.8V) R54.2 R56.2 R58.1 R59.2 R67.2 R70.2 U14.3(VCCA) ; also on sheet 10
VSB_2V8: C74.2 C75.1 C76.1 P8.4(AVDD) P8.23(AF-VCC2.8V) R53.1 R62.1 R68.2 ; also on sheet 10
WL_BOOT_DIS: E1.1 R1.1 U2.6(\\~{CL}R)
WLD_RES: R36.1 R39.2
WLD_SW: D2.ANODE L8.2 U15.1(LX)

Not connected (* = marked no-connect by the designer): FID1 1*; FID2 1*; FID3 1*; FID4 1*; FID5 1*; FID6 1*; P1 2* 4* 6* 7* 8* 9* 16* 18* 45* 49* 50* 51* 52* 53*; P2 12* 14* 18* 20*; P3 2(AUX)* 3(R)* CN* CO*; P4 CN* CO*; P5 CN* CO*; P8 7(NC)* 9(NC)* 17(NC)* 19(NC)* 21(NC)*; P17 6(TX-)* 7(TX+)* 9(RX-)* 10(RX+)*; P22 1* 3* 5* 23*; P45 2*; R179 1*; R181 1*; R198 1*; RN17 1(RA1)* 8(RA2)*; U10 6(CLKOUT)* 16(LOUT)* 17(ROUT)*; U33 2(FLG_A)* 3(FLG_B)*; U35 14(I/O1.4)* 15(I/O1.5)* 16(I/O1.6)* 17(I/O1.7)*

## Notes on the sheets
sheet 1
- SB-UCM-MX8M
- BOARD REVISION: 2.0
- PAGE
- DESCRIPTION
- 01
- Index
- 02
- Carrier-board interface
- 03
- Gigabit Ethernet
- 04
- USB
- 05
- Audio
- 06
- JTAG, CSI, GPIO expander
- 07
- MIPI LCD
- 08
- PCIe
- 09
- Power
- 10
- UART, RS232, SD, EEPROM
- 11
- Mechanical
- 12
- ALT Boot
sheet 2
- V-SOM decoupling capacitors
- Place close to UCM-iMX8M-Mini connectors
sheet 3
- Ethernet connector
- DNP
- 100 Ohm
- 100 Ohm
- 100 Ohm
- 100 Ohm
sheet 4
- USB2.0 OTG
- DNP
- >2.4
- USB2.0 HOST
- 90 ohm
- DNP
sheet 5
- For internal production procedure - do not copy
- Auto alt-boot for internal production procedure
- DNP
- 1-2; Put in ATP
- DNP
- DNP
- "1"-SD
  "0"-WiFi (def.)
- Put in ATP
- DNP
- Auto-reset for internal production procedure
- DNP
- DNP
- DNP
- DNP
- AND
- NOR
- DNP
- DNP
sheet 6
- MIC IN
- Audio Codec
- POWER CONSUMPTION:
  DBVDD = 1.5mA @ 3.3V (typ)
  DCVDD = 3.2mA @ 1.5V (typ) ==> assuming same current @ 3.3V
  HPVDD = 1.7mA @ 3.3V (typ)
  AVDD = 13.1mA @ 3.3V (typ)
  1.5+3.2+1.7+13.1=19.5mA @ 3.3V (typ):
  Assuming worst case is 50mA @ 3.3V
- Place C93 and C94
  ACAP to U10 pins 5 and 4
- Place C97 and C98
  ACAP to U10 pins 3 and 4
- Place C99 and C100
  ACAP to U10 pins 18 and 19
- Place C95 and C170
  ACAP to U10 pins 12 and 15
- AUDIO IN
- I2C ADDRESS: 0b0011010 (0x1AH)
- CP
- CP
- DNP
- AUDIO OUT
- Keep analog signals clear from other signals at least 30mills
  Analog signals list will be provided in separate doc
- DNP
- DNP
- DNP
- DNP
- 20mil
- 20mil
- NOT CP
- Keep S1 close to U11
  S1 width at least 20 mil
- DNP
- SPDIF
sheet 7
- JTAG
- MISC connectors
- NXP refdes layout
- TCK
- TMS
- GND
- VCC
- TDO
- GND
- TDI
- SAI/GPIO
- I2C to GPIO expander
- DNP
- I2C address: 0x20
- I2C connection provision
- DNP
- DNP
- DNP
- LI-OV5640 camera module connector
- Camera module: LI-OV5640-MIPI-AF
- Default I2C address (SCCB slave ID): 0x78
- DNP
- DNP
- DNP
- DNP
- DNP
- up to 140mA
- DNP
- DNP
- DNP
sheet 8
- KD050HDFIA020 LCD connector
- LCD I/O power
- diff 100 ohm
- Vout=Vfb*(1+Rt/Rb)=0.8*(1+13.3/10)=1.86V
- diff 100 ohm
- diff 100 ohm
- diff 100 ohm
- DNP
- diff 100 ohm
- diff 100 ohm
- diff 100 ohm
- diff 100 ohm
- diff 100 ohm
- diff 100 ohm
- LCD back-light power
- DNP
- DNP
- Typical LED configuration: Two parallel chains of 6 serially connected LEDs
- DNP
- DNP
- ALT5-PWM OUT
- KD050HDFIA020 touch-panel connector
- provision
- DNP
- DNP
- I2C addres:0xBA/0xBB or 0x28/0x29
  D. Sheet, page 9
- Pinout of J5 reversed
   to FPC
- DNP
